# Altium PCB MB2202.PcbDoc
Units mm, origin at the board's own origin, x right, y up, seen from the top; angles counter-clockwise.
Board outline 43 x 31 mm, 4 copper layers (Top Layer, Signal Layer 1, Signal Layer 2, Bottom Layer), stack 0.599 mm thick; 44 components, 36 nets, 160 pads, 698 vias.
Unrouted connection lines stored in the file: 92.
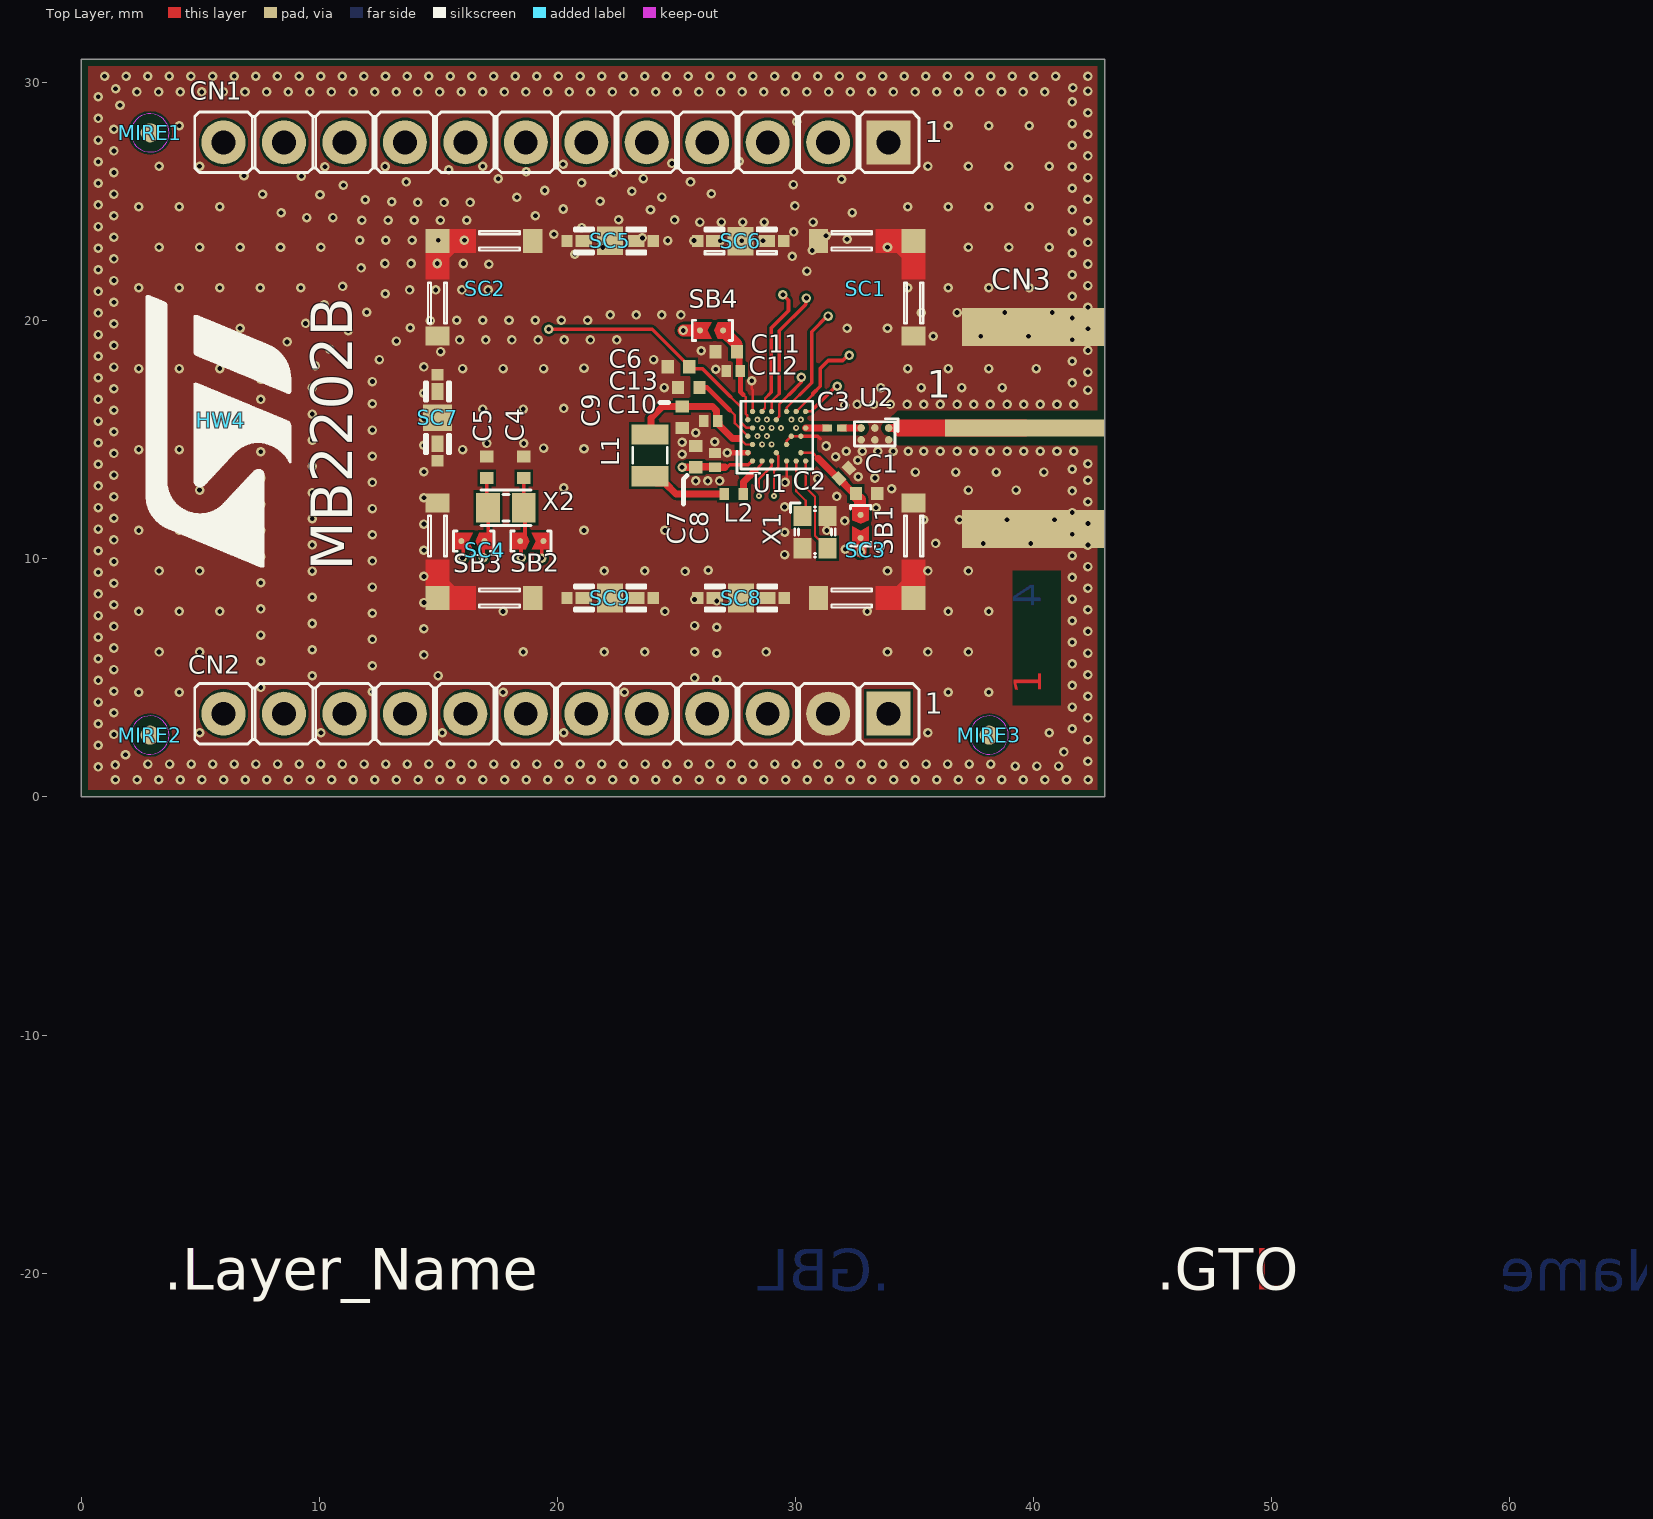
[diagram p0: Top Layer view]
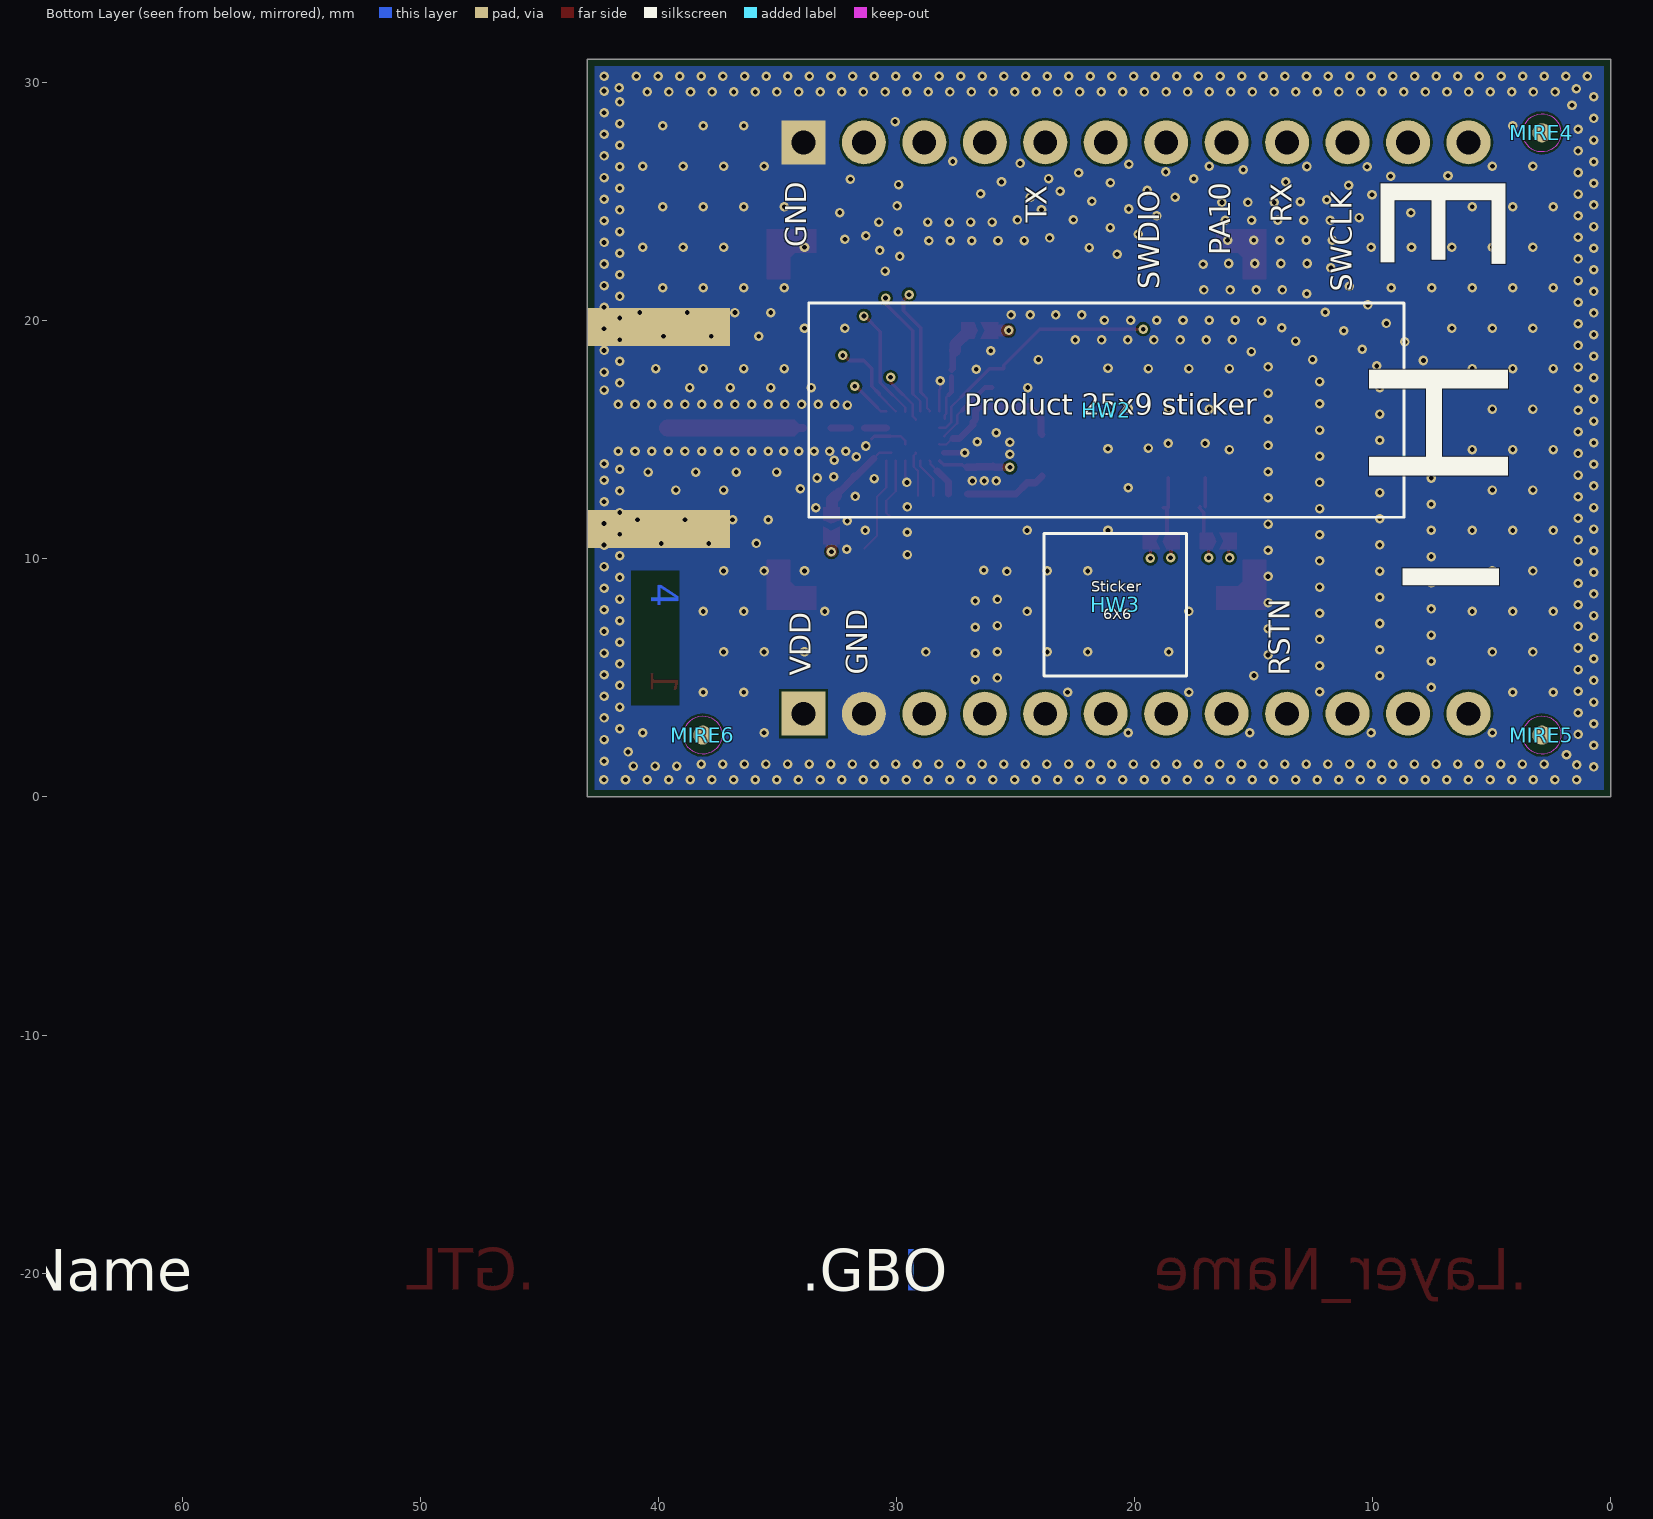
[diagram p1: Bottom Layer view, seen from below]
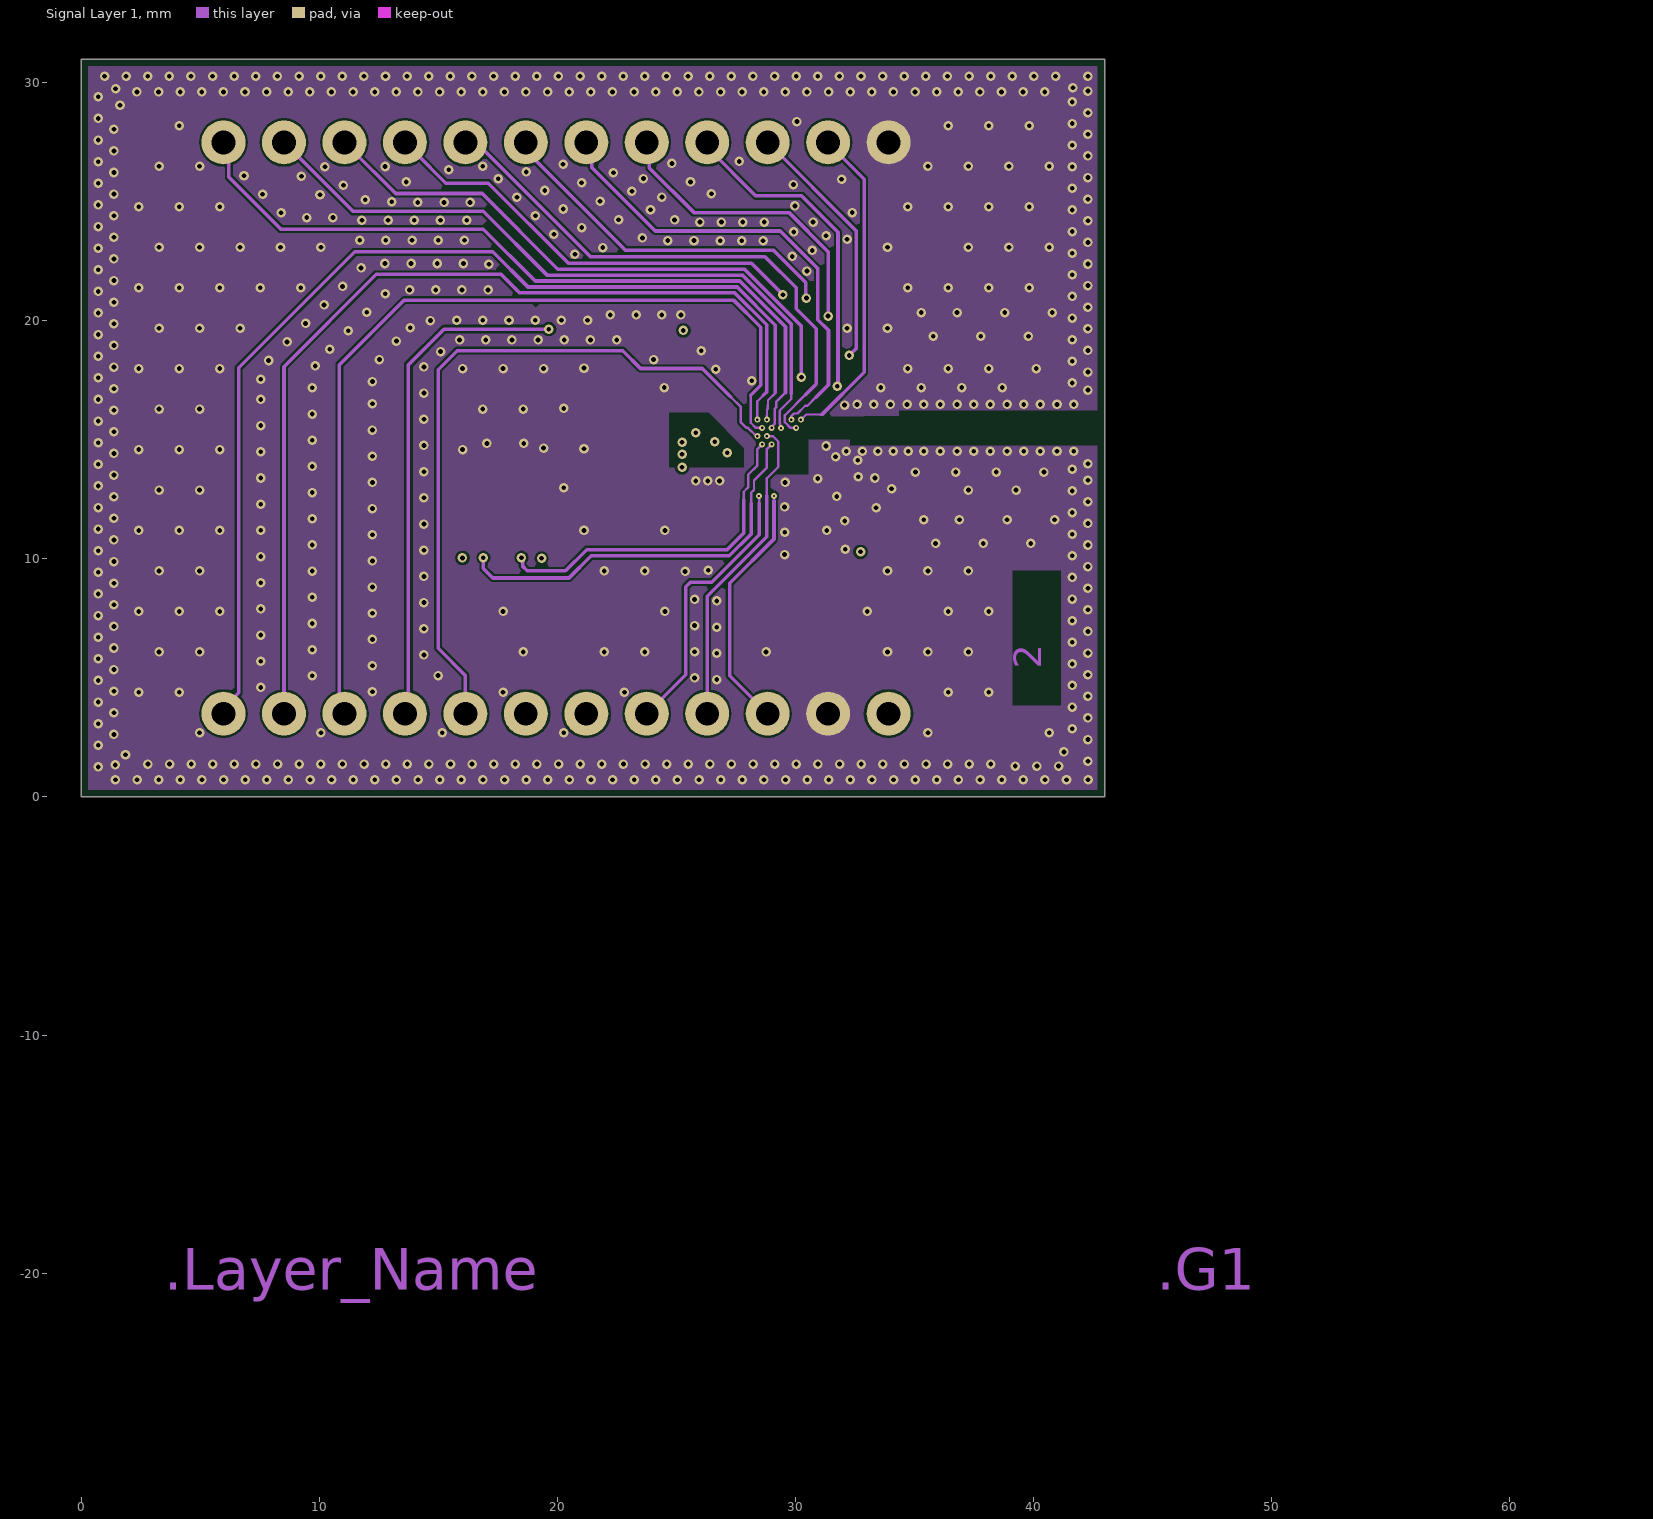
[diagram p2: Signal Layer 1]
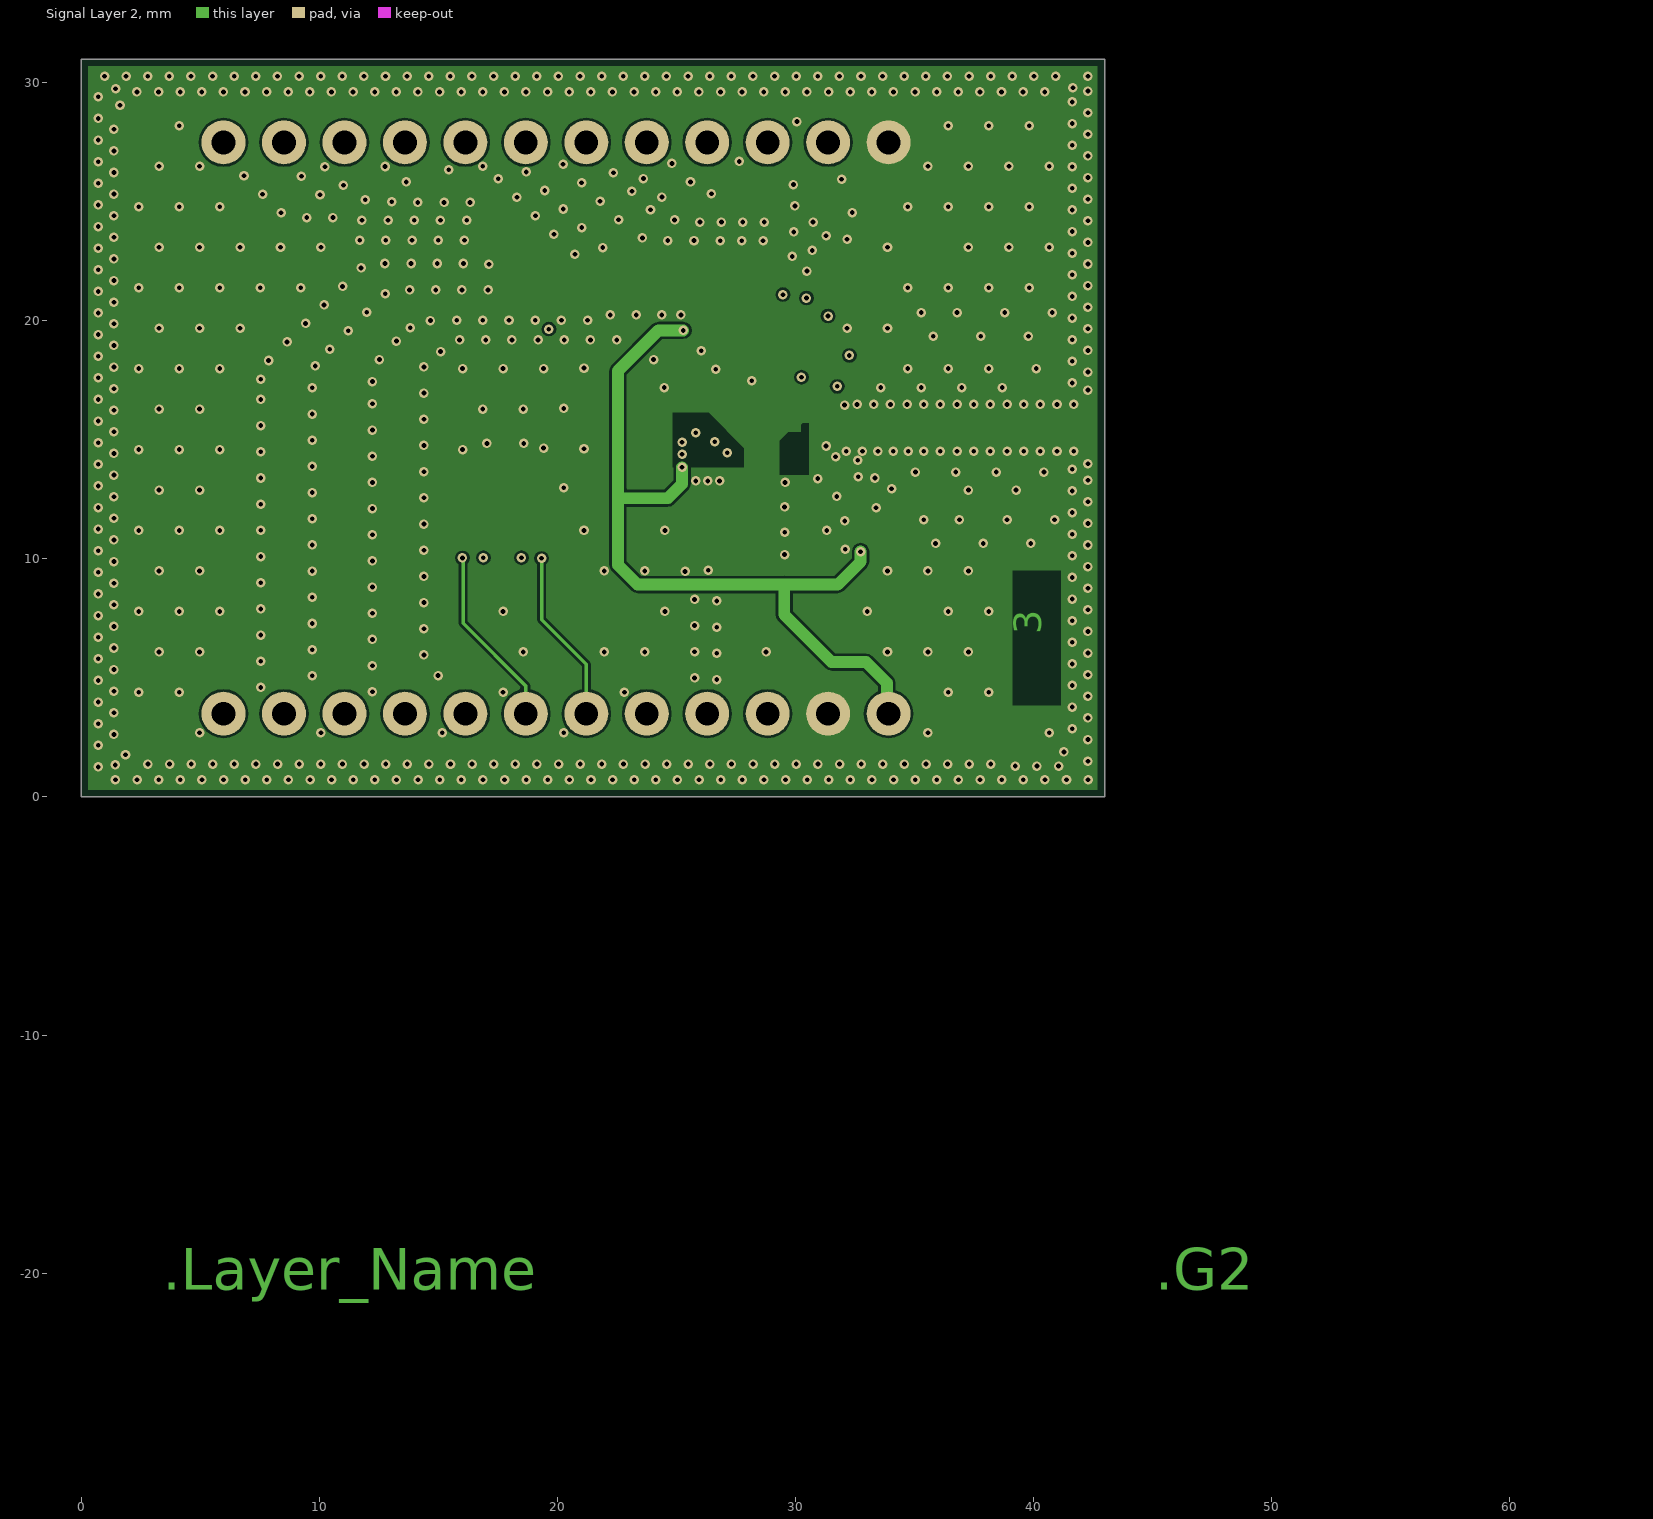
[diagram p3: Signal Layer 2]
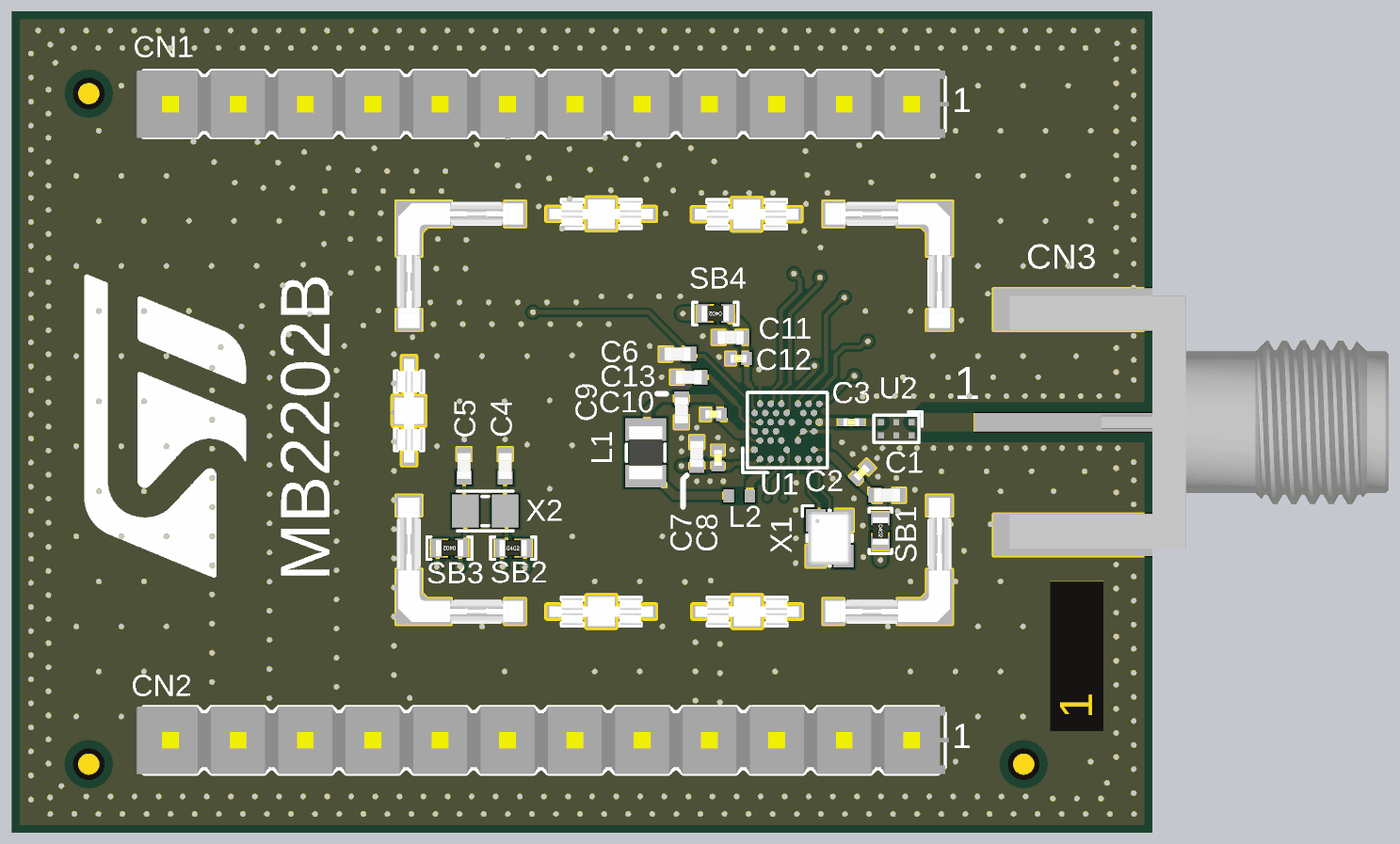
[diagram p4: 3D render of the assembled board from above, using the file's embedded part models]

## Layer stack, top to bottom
Top Solder: solder mask 0.02, Solder Resist, Dk 3.5
Top Layer: signal copper 0.035
Dielectric 1: dielectric 0.102, TU-768 (1x2113), Dk 4.2
Signal Layer 1: signal copper 0.0356
Dielectric2: dielectric 0.254, Tu-768 (2x2113), Dk 4.3
Signal Layer 2: signal copper 0.0356
Dielectric3: dielectric 0.102, TU-768 (1x2113), Dk 4.2
Bottom Layer: signal copper 0.035
Bottom Solder: solder mask 0.02, Solder Resist, Dk 3.5

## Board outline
0,0 0,31 43,31 43,0

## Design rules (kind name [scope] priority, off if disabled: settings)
BoardOutlineClearance [All] p1: gap=0.3 ignorepadtopadclearanceinfootprint=FALSE except(0: Arc-SplitContinuation Track-SplitContinuation SMDPad-SplitContinuation THPad-SplitContinuation Via-SplitContinuation Fill-SplitContinuation Poly-SplitContinuation Region-SplitContinuation Text-SplitContinuation)
Clearance Clearance_RF [InNet('NetC9_2')] p1: gap=0.14 ignorepadtopadclearanceinfootprint=FALSE
Clearance Clearance_RF_1 [InNet('NetC5_1','NetC5_2','NetC9_1')] p2: gap=0.08 ignorepadtopadclearanceinfootprint=FALSE
Clearance [All] p3: gap=0.1 ignorepadtopadclearanceinfootprint=FALSE
HoleToHoleClearance [All] p1: gap=0.15 allowstackedmicrovias=TRUE
MinimumSolderMaskSliver [All] p1: minsoldermaskwidth=0
PlaneClearance [All] p1: clearance=0
PlaneConnect [InNet('GND')] p1: planeconnectstyle=Direct reliefexpansion=0.508 reliefentries=4 reliefconductorwidth=0.254 reliefairgap=0.254
PolygonConnect [InNet('GND')] p1: connectstyle=Direct reliefconductorwidth=0.254 reliefentries=4 polygonreliefangle="90 Angle" airgapwidth=0.254
RoutingVias [All] p1: holewidth=0.2 width=0.4 viastyle="Through Hole" minholewidth=0.2 minwidth=0.4 maxholewidth=0.2 maxwidth=0.4 useviatemplates=TRUE viatemplateguid#1={FA3C43AF-74A2-4DAE-B38C-B4A36A33AEBA} viatemplateguid#2={C3F1866E-02AD-4E07-9877-83EEF2956EBD} viatemplatename#1=v25h10m0 viatemplatename#2=v40h20m0mx0
SMDEntry [All] p1 off: side=TRUE corner=TRUE anyangle=FALSE
SMDNeckDown [All] p1 off: percent=50.000
SMDToCorner [All] p1 off: distance=0
SMDToPlane [All] p1 off: distance=0
SilkToSilkClearance [All] p1: silktosilkclearance=0
SilkToSolderMaskClearance [IsPad] p1: minsilkscreentomaskgap=0 clearancetoexposedcopper=TRUE
SolderMaskExpansion [All] p1: expansion=0.102 istentingtop=FALSE
SupplyNets "Schematic Supply Nets_1" [InNet('VDD')] p1: voltage=0.000
SupplyNets "Schematic Supply Nets" [InNet('GND')] p2: voltage=0.000
ViasUnderSMD [All] p1: allowed=TRUE
Width [All] p1: maxlimit=0.7 minlimit=0.1 preferedwidth=0.1
24 further rules are at their usual default settings.

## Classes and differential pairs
component class Power_Supply: C7 C8 C9 C10 C11 C12 C13 L1 L2 SB4
component class Overview: HW1 HW2 HW3
component class RF_MCU: C1 C2 C3 C4 C5 C6 CN1 CN2 CN3 SB1 SB2 SB3 SC1 SC2 SC3 SC4 SC5 SC6 SC7 SC8 SC9 U1 U2 X1 X2

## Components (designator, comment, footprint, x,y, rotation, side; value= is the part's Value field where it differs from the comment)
C1 "Capacitor" C0402 33,12.75 r180 top value=1uF
C2 "Capacitor" C0201_H0P3#1 32.05,13.6 r225 top value=100nF
C3 "Capacitor" C0201_H0P3#2 31.65,15.494 r0 top value=20pF
C4 "Capacitor" C0402 18.6,13.85 r90 top value=10pF
C5 "Capacitor" C0402 17.05,13.85 r270 top value=10pF
C6 "Capacitor" C0402 25.1,18.075 r180 top value=10nF
C7 "Capacitor" C0402 25.825,14.3 r270 top value=4.7uF
C8 "Capacitor" C0201_H0P3#1 26.625,14.15 r270 top value=100nF
C9 "Capacitor" C0402 25.25,15.95 r90 top value=4.7uF
C10 "Capacitor" C0201_H0P3#1 26.45,15.8 r0 top value=100nF
C11 "Capacitor" C0402 27.1,18.7 r0 top value=1uF
C12 "Capacitor" C0201_H0P3#1 27.4,17.9 r0 top value=100nF
C13 "Capacitor" C0402 25.525,17.2 r0 top value=0.22uF
CN1 "Header 12x1" CON_SAMTEC_TSW-112-07-X-S 19.955,27.5 r180 top locked
CN2 "Header 12x1" CON_SAMTEC_TSW-112-07-X-S 19.955,3.5 r180 top locked
CN3 "SMA-J-P-H-ST-EM1" CON_SMA_AMPHENOL_132415 43,15.5 r90 top value=132415
HW2 "STICKER_PRODUCT" STICKER_PRODUCT_25X9 21.2,16.25 r180 bottom value=N/A
HW3 "STICKER_ES" STICKER_ES_6X6 20.825,8.075 r180 bottom value=N/A
HW4 "Logo" LOGO_ST 5.875,15.825 r90 top
L1 "Inductor" IND_0805_MURATA_LQM21 23.9,14.35 r270 top value=10uH
L2 "Inductor" IND_0402_MURATA_LQG15HSXXXX02_H0P5 27.425,12.725 r0 top value=22nH
MIRE1 "Comment" MIRE_PLACE_SMD_0P8MM 2.9,27.9 r0 top
MIRE2 "Comment" MIRE_PLACE_SMD_0P8MM 2.9,2.6 r0 top
MIRE3 "Comment" MIRE_PLACE_SMD_0P8MM 38.15,2.6 r0 top
MIRE4 "Comment" MIRE_PLACE_SMD_0P8MM 2.9,27.9 r180 bottom
MIRE5 "Comment" MIRE_PLACE_SMD_0P8MM 2.9,2.6 r180 bottom
MIRE6 "Comment" MIRE_PLACE_SMD_0P8MM 38.15,2.6 r180 bottom
SB1 "SB_ON" SOLDER-BRIDGE_R0402-0R 32.75,11.4 r270 top value=0R
SB2 "SB_ON" SOLDER-BRIDGE_R0402-0R 18.9,10.75 r0 top value=0R
SB3 "SB_ON" SOLDER-BRIDGE_R0402-0R 16.5,10.75 r180 top value=0R
SB4 "SB_ON" SOLDER-BRIDGE_R0402-0R 26.525,19.6 r180 top value=0R
SC1 "Shield-clip_S0951-46R" CLIP_HARWIN_S0981-46R 34.975,23.358 r90 top locked value=S0981-46R
SC2 "Shield-clip_S0951-46R" CLIP_HARWIN_S0981-46R 14.975,23.358 r180 top locked value=S0981-46R
SC3 "Shield-clip_S0951-46R" CLIP_HARWIN_S0981-46R 34.975,8.358 r0 top locked value=S0981-46R
SC4 "Shield-clip_S0951-46R" CLIP_HARWIN_S0981-46R 14.975,8.358 r270 top locked value=S0981-46R
SC5 "Shield-clip_S0951-46R" CLIP_HARWIN_S0951-46R 22.225,23.358 r180 top locked value=S0951-46R
SC6 "Shield-clip_S0951-46R" CLIP_HARWIN_S0951-46R 27.71,23.35 r180 top locked value=S0951-46R
SC7 "Shield-clip_S0951-46R" CLIP_HARWIN_S0951-46R 14.975,15.932 r270 top locked value=S0951-46R
SC8 "Shield-clip_S0951-46R" CLIP_HARWIN_S0951-46R 27.725,8.358 r180 top locked value=S0951-46R
SC9 "Shield-clip_S0951-46R" CLIP_HARWIN_S0951-46R 22.225,8.358 r180 top locked value=S0951-46R
U1 "IC_STM32WB09TEF6TR" ICC_WLCSP36_2P83X2P99_P040 29.237,15.197 r90 top value=STM32WB09TEF6TR
U2 "MLPF-WB55-01E3" ICC_CSPG_6BUMPS_1X1P60_P050-P0577 33.35,15.25 r270 top value=MLPF-NRG-01D3
X1 "XTAL_4_PINS" CRY_NX2016SA_4P 30.833,11.125 r270 top value=32MHz
X2 "XTAL_2_PINS" CRY_NX2012SA_2P 17.85,12.15 r180 top value=32.768kHz

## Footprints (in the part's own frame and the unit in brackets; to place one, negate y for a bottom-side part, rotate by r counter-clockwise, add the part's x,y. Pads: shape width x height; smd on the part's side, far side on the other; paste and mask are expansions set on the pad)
C0201_H0P3#1 [mm] "MCD-00699"
  rect 0.4x0.5 smd mask+0.05: 1(-0.3,0) 2(0.3,0)
  body extent -0.32,-0.17 0.32,0.17, height 0.33
C0201_H0P3#2 [mm] "MCD-00699"
  rect 0.4x0.3 smd mask+0.05: 1(-0.3,0) 2(0.3,0)
  body extent -0.32,-0.17 0.32,0.17, height 0.33
C0402 [mm]
  rect 0.51x0.56 smd mask+0.05: 1(-0.45,0) 2(0.45,0)
  body extent -0.5,-0.3 0.5,0.3, height 0.4
CLIP_HARWIN_S0951-46R [mm] "MCD-01587_CLIP-X1"
  rect 0.48x0.5 smd mask+0.1: 1(-1.81,0) 1(1.81,0)
  rect 0.7x0.5 smd mask+0.1: 1(-1.1,0) 1(1.1,0)
  rect 1.1x1.2 smd mask+0.1: 1(0,0)
  silkscreen extent -1.5,-0.55 1.5,0.55, body extent -2.05,-0.65 2.05,0.65, height 1.28
CLIP_HARWIN_S0981-46R [mm] "MCD-02164"
  rect 0.8x1 smd mask+0.05: 1(-4,0)
  rect 1x0.8 smd mask+0.05: 1(0,4)
  rect 1x1 smd mask+0.05: 1(0,0)
  Top Layer region: -1.6,-0.5 0.5,-0.5 0.5,1.6 -0.5,1.6 -0.5,0.7 -0.7,0.5 -1.6,0.5
  silkscreen extent -3.45,-0.4 0.4,3.45, body extent -4.3,-0.46 0.46,4.3, height 1.4
CON_SAMTEC_TSW-112-07-X-S [mm] "MCD-01795"
  rect 1.85x1.85 / inner round 1.85 / far side rect 1.85x1.85 hole 1 mask+0.05: 1(-13.97,0)
  round 1.85 hole 1 mask+0.05: 2(-11.43,0) 3(-8.89,0) 4(-6.35,0) 5(-3.81,0) 6(-1.27,0) 7(1.27,0) 8(3.81,0) 9(6.35,0) 10(8.89,0) 11(11.43,0) 12(13.97,0)
  silkscreen extent -15.24,-1.27 15.18,1.27, body extent -15.37,-1.27 15.24,1.27, height 8.38
CON_SMA_AMPHENOL_132415 [mm] "MCD-04961"
  rect 0.7x6.7 smd mask+0.05: 1(0,3.35)
  rect 1.6x6 smd mask+0.05: 2(-4.25,3) 3(4.25,3)
  rect 1.6x6 smd far side mask+0.05: 4(4.25,3) 5(-4.25,3)
  body extent -4.76,-8.89 4.76,5.38, height 4.08
CRY_NX2012SA_2P [mm]
  rect 1x1.25 smd mask+0.05: 1(-0.75,0) 2(0.75,0)
  silkscreen extent -1.05,-0.75 1.05,0.75, body extent -1.05,-0.63 1.05,0.63, height 0.6
CRY_NX2016SA_4P [mm]
  rect 0.85x0.75 smd mask+0.05: 1(-0.675,-0.525) 2(0.675,-0.525) 3(0.675,0.525) 4(-0.675,0.525)
  silkscreen extent -1.22,-1.02 1.05,0.85, body extent -1.05,-0.85 1.05,0.85, height 0.7
ICC_CSPG_6BUMPS_1X1P60_P050-P0577 [mm] "MCD-03490"
  round 0.32 smd paste-2539.97 mask-0.05: A1(-0.25,0.577) A2(-0.25,0) A3(-0.25,-0.577) B1(0.25,0.577) B2(0.25,0) B3(0.25,-0.577)
  silkscreen extent -0.64,-0.85 0.51,0.97, body extent -0.51,-0.81 0.51,0.81, height 0.7
ICC_WLCSP36_2P83X2P99_P040 [mm] "MCD-04889"
  round 0.225 smd paste+0.012 mask+0.032: A2(-0.736,1.226) A4(-0.043,1.226) A6(0.65,1.226) B1(-1.082,1.026) B3(-0.389,1.026) B5(0.304,1.026) B7(0.996,1.026) C4(-0.043,0.826) C6(0.65,0.826) D1(-1.082,0.626) D3(-0.389,0.626) D5(0.303,0.626) D7(0.996,0.626) E4(-0.043,0.426) E6(0.65,0.426) F1(-1.082,0.226) F3(-0.389,0.226) F5(0.303,0.226) F7(0.996,0.226) G2(-0.736,0.025) G6(0.65,0.025) H5(0.303,-0.175) J1(-1.082,-0.404) J3(-0.389,-0.404) J7(0.996,-0.404) K4(-0.043,-0.605) K6(0.65,-0.605) L1(-1.082,-0.805) L5(0.303,-0.805) L7(0.996,-0.805) M2(-0.736,-1.005) M4(-0.043,-1.005) M6(0.65,-1.005) N1(-1.083,-1.205) N5(0.303,-1.205) N7(0.996,-1.205)
  silkscreen extent -1.6,-1.51 1.43,1.68, body extent -1.43,-1.51 1.43,1.51, height 0.44
IND_0402_MURATA_LQG15HSXXXX02_H0P5 [mm] "MCD-03474"
  rect 0.4x0.5 smd mask+0.05: 1(-0.4,0) 2(0.4,0)
  body extent -0.55,-0.28 0.55,0.28, height 0.55
IND_0805_MURATA_LQM21 [mm] "MCD-02317"
  rect 0.85x1.55 smd mask+0.05: 1(-0.875,0) 2(0.875,0)
  silkscreen extent -0.33,-0.72 0.33,0.72, body extent -1.1,-0.72 1.1,0.72, height 1.45
LOGO_ST [mm]
  silkscreen extent -6.18,-2.95 5.25,3.14
MIRE_PLACE_SMD_0P8MM [mm]
  round 0.8 smd paste-10 mask+0.2: 1(0,0)
  Top Layer keep-out circle w0.01: c0,0 r0.804
SOLDER-BRIDGE_R0402-0R [mil] "MCD-01619"
  round 10 smd paste-393.7: 1(-17.72,0) 2(20.67,0)
  Top Layer region: 1.48,13.78 8.37,0 1.48,-13.78 30.51,-13.78 30.51,13.78
  Top Layer region: -30.51,-13.78 -30.51,13.78 -8.86,13.78 -2.95,0 -8.86,-13.78
  silkscreen extent -33,-17 33,17, body extent -20,-12 20,12, height 14
STICKER_ES_6X6 [mm] "Sticker to mention board QR code 8X8"
  silkscreen extent -3,-3 3,3
STICKER_PRODUCT_25X9 [mm] "Sticker to mention board CPN code"
  silkscreen extent -12.5,-4.5 12.5,4.5

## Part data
C1 C11: library part MCD-03432, "Capacitor, MLCC, 1uF, X7R, 6.3V,+/- 10%, 0402, T=0.5mm", Manufacturer=MURATA, Manufacturer_Part_Number=GRM155R70J105KA12, Package=0402
C2 C8 C10 C12: library part MCD-01535, "Capacitor, MLCC,100nF, 10V, X5R, +/-10%, 0201, T=0.3mm", Manufacturer=MURATA, Manufacturer_Part_Number=GRM033R61A104KE15, Package=0201
C3: library part MCD-03543, "Capacitor, MLCC, 20pF, 25V, COG, +/-2%, 0201, T=0.3mm", Manufacturer=MURATA, Manufacturer_Part_Number=GJM0335C1E200GB01, Package=0201
C4 C5: library part MCD-00015, "Capacitor, MLCC, 10pF, 50V, NPO, +/-5%, 0402, T=0.5mm", Manufacturer=YAGEO, Manufacturer_Part_Number=CC0402JRNPO9BN100, Package=0402
C6: library part MCD-00011, "Capacitor, MLCC, 10nF, 16V, X7R, +/-10%, 0402, T=0.5mm", Manufacturer=YAGEO, Manufacturer_Part_Number=CC0402KRX7R7BB103, Package=0402
C7 C9: library part MCD-03431, "Capacitor, MLCC, 4.7uF, X5R, 10V, +/-20%, 0402, T=0.5mm", Manufacturer=MURATA, Manufacturer_Part_Number=GRM155R61A475MEAAD, Package=0402
C13: library part MCD-03483, "Capacitor, MLCC, 0.22uF, X5R, 6.3V, +/-10%, 0402, T=0.5mm", Manufacturer=YAGEO, Manufacturer_Part_Number=CC0402KRX5R5BB224, Package=0402
CN1 CN2: library part MCD-01795, "Header, 12x1, 2.54mm, VR, TH, T=5.84mm/2.54mm", Manufacturer=SAMTEC, Manufacturer_Part_Number=TSW-112-07-T-S
CN3: library part MCD-04961, "Jack_SMA, VR, PCB edge, 50R, T=7.92mm", Manufacturer=AMPHENOL, Manufacturer_Part_Number=132415
HW2: library part MCD-00547, "Sticker product, 25x9mm", Manufacturer=N/A, Manufacturer_HQ_COO=Unknown
HW3: library part MCD-00234, "Sticker ES, 6x6mm", Manufacturer=N/A
HW4: library part MCD-00625, "\"STMicroelectronics\" logo footprint for PCB"
L1: library part MCD-03438, "Inductor, MLCC, 10uH, +/-20%, 300mA, 845mR, 0805, T=1.45mm", Manufacturer=MURATA, Manufacturer_Part_Number=LQM21DN100M70L, Package=0805
L2: library part MCD-03439, "Inductor, MLCC, 22nH, +/-2%, 350mA, 0.58R, 0402, T=1.45mm", Manufacturer=MURATA, Manufacturer_Part_Number=LQW15AN22NG00, Package=0402
SB1 SB2 SB3 SB4: library part MCD-01618, "Resistor, 0R, SB0402, 5%, 0.063W", Manufacturer=YAGEO, Manufacturer_Part_Number=RC0402JR-070RL, Package=0402
SC1 SC2 SC3 SC4: library part MCD-02164, "Shield clip Harwin S0981-46R to fix RF shielded cavity", Manufacturer=HARWIN, Manufacturer_Part_Number=S0981-46R, Package=0.8x4.7x1.4mm
SC5 SC6 SC7 SC8 SC9: library part MCD-01587, "RFI shield clip mini TIN SMD", Manufacturer=HARWIN, Manufacturer_Part_Number=S0951-46R, Package=1.1x3.9mm
U1: library part MCD-04889, "MCU, ARM Cortex-M0+ 32-bit, 512KB Flash, 64KB RAM, With Crypto", Manufacturer=STMICROELECTRONICS, Manufacturer_Part_Number=STM32WB09TEF6TR, Package=WLCSP36
U2: library part MCD-03490, "2.4 GHz low pass filter matched to BLUENRG-LP-LPS", Manufacturer=STMICROELECTRONICS, Manufacturer_Part_Number=MLPF-NRG-01D3, Package=CSP
X1: library part MCD-01446, "Crystal, 32MHz, 8pF, +/-10ppm, 60R, 2x1.6mm", Manufacturer=NDK, Manufacturer_Part_Number=NX2016SA-32MHZ-EXS00A-CS06654, Package=2x1.6mm
X2: library part MCD-01445, "Crystal, 32.768kHz, 7pF, +/-20ppm, 80K, 2.05x1.2mm", Manufacturer=NDK, Manufacturer_Part_Number=NX2012SA-32.768KHZ-EXS00A-MU00389, Package=2.05x1.2mm

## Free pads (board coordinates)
  round 0.508 on Mech16: 1(15.17,-27.648) 1(64.017,-27.648)

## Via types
v1: diameter 0.4, hole 0.2, Top Layer to Bottom Layer, tented both sides, 684 vias
v2: diameter 0.25, hole 0.1, Top Layer to Signal Layer 1, tented both sides, 14 vias

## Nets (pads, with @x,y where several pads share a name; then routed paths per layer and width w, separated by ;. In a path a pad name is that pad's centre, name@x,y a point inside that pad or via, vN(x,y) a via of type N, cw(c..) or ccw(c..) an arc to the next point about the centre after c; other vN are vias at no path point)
GND: C1.1 C2.1 C4.2 C5.1 C6.2 C7.1 C8.1 C9.1 C10.1 C11.1 C12.1 C13.1 CN1.1 CN2.2 CN3.2 CN3.3 CN3.4 CN3.5 SC1.1 SC2.1 SC3.1 SC4.1 SC5.1 SC6.1 SC7.1 SC8.1 SC9.1 U1.A2 U1.B7 U1.J1 U1.J3 U1.K4 U1.M4 U2.A2 U2.B1 U2.B2 U2.B3 X1.2 X1.4 | length 4.8
  Top Layer w0.1: v1(28.175,17.485) 28.175,17.153 28.212,17.116 U1.B7 ; v1(29.574,13.214) 29.574,13.295 29.642,13.364 U1.J1@29.642,14.12 ; U1.J3@29.642,14.813 29.642,14.96 29.842,15.16 U1.M4@30.242,15.16
  Top Layer w0.148: U1.M4@30.247,15.158 30.942,15.158 31.05,15.05
  Top Layer w0.25: v1(27.15,14.461) 27.55,14.461 ; 27.573,14.461 U1.A2@28.012,14.461
  other v1: 1.447,0.72 2.355,0.72 3.263,0.72 4.171,0.72 5.079,0.72 5.987,0.72 6.895,0.72 7.803,0.72 8.711,0.72 9.619,0.72 10.527,0.72 11.435,0.72 12.343,0.72 13.251,0.72 14.159,0.72 15.067,0.72 15.975,0.72 16.883,0.72 17.791,0.72 18.699,0.72 19.607,0.72 20.515,0.72 21.423,0.72 22.331,0.72 23.239,0.72 24.147,0.72 25.055,0.72 25.963,0.72 26.871,0.72 27.779,0.72 28.687,0.72 29.595,0.72 30.503,0.72 31.411,0.72 32.319,0.72 33.227,0.72 34.135,0.72 35.043,0.72 35.951,0.72 36.859,0.72 37.767,0.72 38.675,0.72 39.583,0.72 40.491,0.72 41.399,0.72 42.307,0.72 0.72,1.264 39.25,1.3 40.158,1.3 41.066,1.3 1.441,1.347 2.809,1.38 3.717,1.38 4.625,1.38 5.533,1.38 6.441,1.38 7.349,1.38 8.257,1.38 9.165,1.38 10.073,1.38 10.981,1.38 11.889,1.38 12.797,1.38 13.705,1.38 14.613,1.38 15.521,1.38 16.429,1.38 17.337,1.38 18.245,1.38 19.153,1.38 20.061,1.38 20.969,1.38 21.877,1.38 22.785,1.38 23.693,1.38 24.601,1.38 25.509,1.38 26.417,1.38 27.325,1.38 28.233,1.38 29.141,1.38 30.049,1.38 30.957,1.38 31.865,1.38 32.773,1.38 33.681,1.38 34.589,1.38 35.497,1.38 36.405,1.38 37.313,1.38 38.221,1.38 42.3,1.505 1.867,1.776 41.293,1.894 0.72,2.172 42.3,2.413 1.38,2.626 4.979,2.695 10.079,2.695 15.179,2.695 20.279,2.695 35.579,2.695 40.679,2.695 41.64,2.867 0.72,3.08 42.3,3.321 1.38,3.534 41.64,3.775 0.72,3.988 42.3,4.229 2.429,4.395 4.129,4.395 17.729,4.395 22.829,4.395 36.429,4.395 38.129,4.395 12.239,4.416 1.38,4.442 7.55,4.6 41.64,4.683 0.72,4.896 26.702,4.933 25.775,5 9.714,5.087 15,5.1 42.3,5.137 1.38,5.35 12.239,5.516 41.64,5.591 7.55,5.7 0.72,5.804 14.403,5.965 26.702,6.033 42.3,6.045 3.279,6.095 4.979,6.095 18.579,6.095 21.979,6.095 23.679,6.095 25.775,6.1 28.779,6.095 33.879,6.095 35.579,6.095 37.279,6.095 9.714,6.187 1.38,6.258 41.64,6.499 12.239,6.616 0.72,6.712 7.55,6.8 42.3,6.953 14.403,7.065 26.702,7.133 1.38,7.166 25.775,7.2 9.714,7.287 41.64,7.407 0.72,7.62 12.239,7.716 2.429,7.795 4.129,7.795 5.829,7.795 17.729,7.795 24.529,7.795 33.029,7.795 36.429,7.795 38.129,7.795 42.3,7.861 7.55,7.9 1.38,8.074 14.403,8.165 26.702,8.233 25.775,8.3 41.64,8.315 9.714,8.387 0.72,8.528 42.3,8.769 12.239,8.816 1.38,8.982 7.55,9 41.64,9.223 14.403,9.265 0.72,9.436 25.375,9.475 3.279,9.495 4.979,9.495 9.714,9.487 21.979,9.495 23.679,9.495 33.879,9.495 35.579,9.495 37.279,9.495 26.35,9.525 42.3,9.677 1.38,9.89 12.239,9.916 7.55,10.1 41.64,10.131 29.554,10.185 0.72,10.344 14.403,10.365 32.106,10.408 9.714,10.587 42.3,10.585 35.9,10.65 37.9,10.65 39.9,10.65 1.38,10.798 12.239,11.016 41.64,11.039 29.56,11.12 2.429,11.195 4.129,11.195 5.829,11.195 7.55,11.2 21.129,11.195 24.529,11.195 31.329,11.195 0.72,11.252 14.403,11.465 42.3,11.493 32.084,11.599 35.4,11.65 36.9,11.65 38.9,11.65 40.9,11.65 9.714,11.687 1.38,11.706 41.64,11.947 12.239,12.116 0.72,12.16 33.4,12.15 29.555,12.185 7.55,12.3 42.3,12.401 14.403,12.565 1.38,12.614 31.75,12.625 9.714,12.787 41.64,12.855 3.279,12.895 4.979,12.895 37.279,12.895 39.279,12.895 34.05,12.95 20.283,12.985 0.72,13.068 12.239,13.216 25.825,13.275 26.325,13.275 26.825,13.275 42.3,13.309 30.948,13.373 7.55,13.4 33.35,13.4 32.65,13.45 1.38,13.522 14.403,13.665 35.05,13.65 36.75,13.65 38.45,13.65 40.45,13.65 41.64,13.763 9.714,13.887 0.72,13.976 42.3,13.995 32.625,14.15 31.7,14.294 12.239,14.316 25.25,14.4 1.38,14.43 7.55,14.5 32.15,14.525 32.825,14.525 33.475,14.525 34.125,14.525 34.75,14.525 35.402,14.525 36.1,14.525 36.8,14.525 37.5,14.525 38.2,14.525 38.9,14.525 39.6,14.525 40.3,14.525 41,14.525 41.7,14.525 2.429,14.595 4.129,14.595 5.829,14.595 16.029,14.595 21.129,14.63 19.429,14.655 31.3,14.744 14.403,14.765 17.05,14.85 18.6,14.85 0.72,14.884 25.25,14.9 26.625,14.925 9.714,14.987 25.825,15.3 1.38,15.338 12.239,15.416 7.55,15.6 0.72,15.792 14.403,15.865 9.714,16.087 1.38,16.246 3.279,16.295 4.979,16.295 16.879,16.295 18.579,16.295 20.279,16.32 32.077,16.465 32.602,16.49 33.302,16.49 34.002,16.49 34.702,16.49 35.402,16.49 36.1,16.49 36.8,16.49 37.5,16.49 38.2,16.49 38.9,16.49 39.6,16.49 40.3,16.49 41,16.49 41.7,16.49 12.239,16.516 0.72,16.7 7.55,16.7 14.403,16.965 42.3,17.095 1.38,17.154 9.714,17.187 24.5,17.2 33.6,17.2 35.3,17.2 37,17.2 38.7,17.2 41.64,17.395 12.239,17.45 7.55,17.55 0.72,17.608 42.3,17.849 26.665,17.965 2.429,17.995 4.129,17.995 5.829,17.995 16.029,17.995 17.729,17.995 19.429,17.995 34.729,17.995 36.429,17.995 38.129,17.995 40.129,17.995 21.129,18.02 1.38,18.062 14.403,18.065 9.834,18.11 41.64,18.303 7.877,18.336 12.534,18.375 24.05,18.375 0.72,18.516 15.103,18.71 26.05,18.75 42.3,18.757 10.448,18.806 1.38,18.97 8.655,19.114 13.25,19.15 15.9,19.2 17,19.2 18.1,19.2 19.2,19.2 20.3,19.2 21.4,19.2 22.5,19.2 41.64,19.211 35.8,19.35 37.8,19.35 39.8,19.35 0.72,19.424 11.225,19.584 42.3,19.665 3.279,19.695 4.979,19.695 6.679,19.695 13.829,19.711 32.179,19.695 33.879,19.695 1.38,19.878 9.433,19.891 14.679,20.011 15.779,20.025 16.879,20.025 17.979,20.025 19.079,20.025 20.179,20.025 21.279,20.025 41.64,20.119 22.229,20.25 23.325,20.25 24.4,20.25 25.2,20.25 0.72,20.332 35.3,20.35 36.8,20.35 38.8,20.35 40.8,20.35 12.003,20.362 42.3,20.573 10.211,20.669 1.38,20.786 41.64,21.027 12.781,21.139 0.72,21.24 13.8,21.3 14.9,21.3 16,21.3 17.1,21.3 2.429,21.395 4.129,21.395 5.829,21.395 7.529,21.395 9.229,21.395 34.729,21.395 36.429,21.395 38.129,21.395 39.829,21.395 10.989,21.447 42.3,21.481 1.38,21.694 41.64,21.935 30.495,22.092 0.72,22.148 11.766,22.225 17.137,22.382 42.3,22.389 12.766,22.411 13.866,22.411 14.966,22.411 16.066,22.411 1.38,22.602 29.877,22.709 20.75,22.8 41.64,22.843 30.721,22.959 0.72,23.056 3.279,23.095 4.979,23.095 6.679,23.095 8.379,23.095 10.079,23.095 21.92,23.08 33.879,23.095 37.279,23.095 38.979,23.095 40.679,23.095 42.3,23.297 24.65,23.375 25.75,23.375 26.853,23.371 27.753,23.371 28.653,23.371 11.705,23.389 12.805,23.389 13.905,23.389 15.005,23.389 16.105,23.389 32.179,23.425 23.582,23.487 1.38,23.51 31.3,23.575 19.865,23.642 29.943,23.737 41.64,23.751 21.035,23.922 0.72,23.964 26,24.15 26.9,24.15 27.8,24.15 28.7,24.15 30.75,24.15 42.3,24.205 11.8,24.225 12.9,24.225 14,24.225 15.1,24.225 16.2,24.225 24.935,24.239 22.581,24.25 9.483,24.339 10.583,24.339 1.38,24.418 19.087,24.42 8.402,24.54 32.4,24.55 23.923,24.669 41.64,24.659 20.257,24.7 2.429,24.795 4.129,24.795 5.829,24.795 34.729,24.795 36.429,24.795 38.129,24.795 39.829,24.795 29.989,24.831 0.72,24.872 14.15,24.975 15.25,24.975 16.345,24.975 13.05,25 21.803,25.028 11.942,25.089 42.3,25.113 18.309,25.198 24.405,25.203 10.039,25.295 1.38,25.326 7.624,25.318 26.483,25.339 23.145,25.447 19.479,25.478 41.64,25.567 11.023,25.693 29.925,25.725 0.72,25.78 21.025,25.806 13.661,25.839 25.603,25.839 31.95,25.95 17.531,25.976 23.628,25.981 42.3,26.021 9.261,26.073 6.846,26.095 1.38,26.234 22.367,26.225 18.701,26.256 15.45,26.346 10.245,26.471 3.279,26.495 4.979,26.495 12.771,26.485 16.879,26.495 35.579,26.495 37.279,26.495 38.979,26.495 40.679,26.495 41.64,26.475 20.248,26.584 24.825,26.616 0.72,26.688 27.65,26.7 42.3,26.929 1.38,27.142 41.64,27.383 0.72,27.596 42.3,27.837 1.38,28.05 4.129,28.195 36.429,28.195 38.129,28.195 39.829,28.195 41.64,28.291 30.075,28.375 0.72,28.504 42.3,28.745 1.637,29.062 41.64,29.199 0.72,29.412 2.348,29.62 3.256,29.62 4.164,29.62 5.072,29.62 5.98,29.62 6.888,29.62 7.796,29.62 8.704,29.62 9.612,29.62 10.52,29.62 11.428,29.62 12.336,29.62 13.244,29.62 14.152,29.62 15.06,29.62 15.968,29.62 16.876,29.62 17.784,29.62 18.692,29.62 19.6,29.62 20.508,29.62 21.416,29.62 22.324,29.62 23.232,29.62 24.14,29.62 25.048,29.62 25.956,29.62 26.864,29.62 27.772,29.62 28.68,29.62 29.588,29.62 30.496,29.62 31.404,29.62 32.312,29.62 33.22,29.62 34.128,29.62 35.036,29.62 35.944,29.62 36.852,29.62 37.76,29.62 38.668,29.62 39.576,29.62 40.484,29.62 42.3,29.653 1.45,29.75 41.67,29.795 0.986,30.28 1.894,30.28 2.802,30.28 3.71,30.28 4.618,30.28 5.526,30.28 6.434,30.28 7.342,30.28 8.25,30.28 9.158,30.28 10.066,30.28 10.974,30.28 11.882,30.28 12.79,30.28 13.698,30.28 14.606,30.28 15.514,30.28 16.422,30.28 17.33,30.28 18.238,30.28 19.146,30.28 20.054,30.28 20.962,30.28 21.87,30.28 22.778,30.28 23.686,30.28 24.594,30.28 25.502,30.28 26.41,30.28 27.318,30.28 28.226,30.28 29.134,30.28 30.042,30.28 30.95,30.28 31.858,30.28 32.766,30.28 33.674,30.28 34.582,30.28 35.49,30.28 36.398,30.28 37.306,30.28 38.214,30.28 39.122,30.28 40.03,30.28 40.938,30.28 42.3,30.275
IPF_IN: C3.2 U2.A3 | length 0.8
  Top Layer w0.3: C3.2 U2.A3@32.773,15.494
NetL1_2: L1.2 L2.1 | length 3.4
  Top Layer w0.3: L1.2 24.175,13.2 24.525,13.2 25,12.725 L2.1
PA0: CN1.3 U1.L7 | length 14.3
  Top Layer w0.1: U1.L7@30.042,16.199 30.746,16.903
  Top Layer w0.15: 30.746,16.903 30.746,16.95 31.05,17.254 31.05,18 31.386,18.336 31.994,18.336 32.209,18.55 v1(32.275,18.55)
  Signal Layer 1 w0.15: CN1.3 32.575,23.77 32.575,18.851 v1@32.275,18.551
PA1: CN1.5 U1.J7 | length 17.7
  Top Layer w0.1: U1.J7@29.646,16.189 29.646,16.357 30.192,16.903
  Top Layer w0.15: 30.192,16.903 30.696,17.407 30.696,19.546 31.352,20.202 v1(31.384,20.202)
  Signal Layer 1 w0.15: CN1.5@23.65,27.6 23.875,27.375 23.875,26.425 25.75,24.55 29.74,24.55 31.394,22.897 v1@31.394,20.204
PA2: CN1.7 U1.F7 | length 20.4
  Top Layer w0.1: U1.F7@29.013,16.199 29.013,16.624 29.337,16.948
  Top Layer w0.15: 29.337,16.948 29.337,19.587 30.44,20.69 30.44,20.929 v1(30.471,20.96)
  Signal Layer 1 w0.15: CN1.7 18.685,27.155 22.865,22.975 29.081,22.975 30.446,21.61 v1@30.446,20.991
PA3: CN1.10 U1.G6 | length 26.9
  Top Layer w0.1: U1.G6@29.213,15.852 29.213,15.872 29.327,15.986 29.327,16.49 29.739,16.903
  Top Layer w0.15: 29.739,16.903 30.262,17.426 v1(30.262,17.632) v1@30.215,17.585
  Signal Layer 1 w0.15: CN1.10@10.9,27.25 11.315,27.25 13.215,25.35 16.858,25.35 20.033,22.175 27.875,22.175 30.262,19.788 v1(30.262,17.632)
PA8: CN1.4 U1.N7 | length 15.4
  Top Layer w0.1: U1.N7@30.442,16.199 30.661,16.199 30.824,16.362
  Top Layer w0.15: 30.824,16.362 31.715,17.253 v1(31.769,17.253)
  Signal Layer 1 w0.15: CN1.4 26.305,27.295 28.35,25.25 30.275,25.25 31.8,23.725 31.8,17.284 v1(31.769,17.253)
PA9: CN1.6 U1.K6 | length 19.3
  Signal Layer 1 w0.1: v2(29.842,15.852) 29.842,16 29.952,16.109 30.097,16.109 30.424,16.436 30.516,16.436 30.878,16.798
  Signal Layer 1 w0.15: CN1.6@21.2,27.05 21.462,26.788 21.462,26.438 24.125,23.775 29.375,23.775 30.95,22.2 30.95,20.05 31.4,19.6 31.4,17.32 30.878,16.798
PA10: CN1.8 U1.L5 | length 23.5
  Signal Layer 1 w0.1: v2(30.043,15.506) 29.8,15.506 29.567,15.738 29.567,15.756 29.565,15.758 29.565,16.031 30.438,16.903
  Signal Layer 1 w0.15: CN1.8 16.456,27.189 16.911,27.189 21.4,22.7 28.731,22.7 30.042,21.389 30.042,20.508 30.886,19.664 30.886,17.352 30.438,16.903
PA11: CN1.2 U1.M6 | length 13.8
  Signal Layer 1 w0.1: v2(30.242,15.852) 30.463,16.066 30.504,16.066 31.082,16.057 ccw(c31.083,16.157) 31.083,16.057 31.117,16.057 31.131,16.07
  Signal Layer 1 w0.15: 31.131,16.07 32.9,17.839 32.9,25.95 31.385,27.465 CN1.2
PB0: CN1.9 U1.D7 | length 23.7
  Top Layer w0.1: U1.D7@28.613,16.199 28.613,16.226 28.733,16.347 28.733,16.741 28.895,16.903
  Top Layer w0.15: 28.895,16.903 29.002,17.009 29.002,19.702 29.721,20.421 29.721,20.868 v1(29.487,21.102)
  Signal Layer 1 w0.15: CN1.9@13.7,27.05 14.055,27.05 15.316,25.789 17.112,25.789 20.476,22.425 28.164,22.425 v1(29.487,21.102)
PB1: CN2.12 U1.E6 | length 44.6
  Signal Layer 1 w0.1: v2(28.813,15.852) 28.816,16.276 28.856,16.315 28.858,16.668 29.168,16.973
  Signal Layer 1 w0.15: CN2.12@6.1,3.6 6.1,3.855 6.625,4.38 6.625,18.025 11.5,22.9 17.3,22.9 18.775,21.425 27.564,21.425 29.168,19.821 29.168,16.973
PB2: CN2.10 U1.D5 | length 38.8
  Signal Layer 1 w0.1: 28.137,16.877 28.137,15.717 28.349,15.506 v2(28.613,15.506)
  Signal Layer 1 w0.15: CN2.10 10.85,3.715 10.85,18.15 13.575,20.875 27.407,20.875 28.55,19.732 28.55,17.289 28.137,16.877
PB3: CN2.11 U1.C6 | length 41.3
  Signal Layer 1 w0.1: v2(28.412,15.853) 28.413,16.625 28.666,16.878
  Signal Layer 1 w0.15: CN2.11@8.4,3.75 8.525,3.875 8.525,18.075 12.406,21.956 17.1,21.956 ; 17.113,21.956 17.644,21.956 18.425,21.175 27.461,21.175 28.8,19.836 28.8,17.012 28.666,16.878
PB4: CN1.12 U1.F5 | length 31.9
  Signal Layer 1 w0.1: v2(29.013,15.506) 29.013,15.547 29.149,15.683 29.149,16.318 29.213,16.381 29.213,16.607 29.593,16.988
  Signal Layer 1 w0.15: CN1.12@5.85,27.35 6.212,26.988 6.212,26.038 8.4,23.85 16.9,23.85 19.075,21.675 27.668,21.675 29.593,19.75 29.593,16.988
PB5: CN1.11 U1.H5 | length 29
  Signal Layer 1 w0.1: v2(29.407,15.496) 29.379,15.525 29.379,15.645 29.349,15.674 29.349,16.235 29.843,16.729 29.843,16.939
  Signal Layer 1 w0.15: CN1.11@8.575,27.45 11.425,24.6 16.9,24.6 19.575,21.925 27.771,21.925 29.843,19.853 29.843,16.939
PB6: CN2.8 U1.C4 | length 30.5
  Signal Layer 1 w0.1: 27.286,16.814 27.719,16.381 27.719,15.736 27.949,15.506 28.016,15.506 28.363,15.16 v2(28.413,15.16)
  Signal Layer 1 w0.15: CN2.8 16.145,5.105 15,6.25 15,17.95 15.8,18.75 22.751,18.75 23.501,18 26.1,18 27.286,16.814
PB7: CN2.4 U1.E4 | length 13.2
  Signal Layer 1 w0.1: 28.803,12.661 28.803,13.384 29.287,13.868 29.287,14.933 29.061,15.16 v2(28.813,15.16)
  Signal Layer 1 w0.15: CN2.4 26.305,8.43 28.8,10.925 28.8,12.661
PB12: CN2.6 SB2.2 | length 8
  Top Layer w0.15: v1@19.35,10.011 SB2.2@19.35,10.733
  Signal Layer 2 w0.15: v1@19.35,10.022 19.35,7.45 21.225,5.575 CN2.6
  other v1: 19.349,10.026
PB13: CN2.7 SB3.2 | length 8.8
  Top Layer w0.15: v1@16.05,10.031 SB3.2@16.05,10.713
  Signal Layer 2 w0.15: v1@16.05,10.016 16.05,7.3 18.685,4.665 CN2.7@18.685,3.65 ; CN2.7@18.535,3.65 CN2.7@18.685,3.65 ; CN2.7 CN2.7@18.685,3.65 ; CN2.7@19.002,3.709 18.943,3.65 CN2.7@18.685,3.65
  other v1: 16.022,10.04
PB14: CN2.5 U1.F1 | length 13.3
  Top Layer w0.1: v2(28.478,12.646) 28.478,13.353 29.012,13.887 U1.F1@29.012,14.121
  Signal Layer 1 w0.1: v2(28.478,12.646) 28.487,12.637 28.487,12.33
  Signal Layer 1 w0.15: CN2.5 25.4,5.135 25.4,8.825 25.6,9.025 26.5,9.025 28.487,11.012 28.487,12.33
PB15: CN2.3 U1.G2 | length 12.5
  Top Layer w0.1: v2@29.112,12.649 29.112,13.693 29.29,13.871 29.29,14.342 29.212,14.419 U1.G2@29.212,14.467
  Signal Layer 1 w0.1: 29.112,12.45 v2(29.112,12.646)
  Signal Layer 1 w0.15: CN2.3 27.25,5.095 27.25,8.975 29.112,10.837 29.112,12.45
RF_OUT: C3.1 U1.N5 | length 0.9
  Top Layer w0.3: U1.N5@30.442,15.494 C3.1
RSTN: C6.1 CN2.9 U1.B5 | length 31.9
  Top Layer w0.1: 27.286,16.814 27.719,16.381 27.719,15.736 27.949,15.506 U1.B5@28.213,15.506
  Top Layer w0.15: v1(19.65,19.65) 24,19.65 25.507,18.143 25.507,17.993 26.107,17.993 27.286,16.814
  Signal Layer 1 w0.15: CN2.9@13.55,3.55 13.75,3.75 13.75,18.122 ; 13.75,18.15 15.25,19.65 v1(19.65,19.65)
SMA_IN: CN3.1 U2.A1 | length 5.3
  Top Layer w0.32: U2.A1 34.363,15.5
  Top Layer w0.7: 34.825,15.5 CN3.1
VCAP_A4: C13.2 U1.A4 | length 3.1
  Top Layer w0.1: 27.25,16.25 27.46,16.04 27.46,15.706 28.006,15.16 U1.A4@28.013,15.16
  Top Layer w0.2: C13.2@26,17.2 26.3,17.2 27.25,16.25
VDD: C7.2 C8.2 CN2.1 SB1.2 SB4.2 U1.B1 | length 39
  Top Layer w0.1: U1.B1@28.193,14.114 U1.B1
  Top Layer w0.15: 27.15,13.85 27.25,13.95 28.029,13.95 U1.B1@28.193,14.114
  Top Layer w0.3: v1(25.25,13.85) 25.9,13.85 25.95,13.9 25.975,13.875 26.625,13.875 26.65,13.85 27.05,13.85
  Top Layer w0.5: v1(25.3,19.6) SB4.2 ; v1(32.75,10.3) SB1.2
  Signal Layer 2 w0.5: 22.553,12.55 24.65,12.55 25.25,13.15 v1(25.25,13.85) ; 22.553,13.012 22.553,9.751 23.38,8.924 31.784,8.924 32.75,9.889 v1@32.75,10.316 ; 22.553,13.034 22.553,17.894 24.259,19.6 v1(25.3,19.6) ; 29.541,8.931 29.541,7.659 31.535,5.665 32.983,5.665 33.852,4.796 33.852,3.573 CN2.1
VDD2_A6_IN: C11.2 C12.2 SB4.1 U1.A6 | length 3.9
  Top Layer w0.1: 27.812,16.903 27.925,16.789 27.925,16.088 27.984,16.03 U1.A6@27.984,15.881
  Top Layer w0.2: C12.2@27.7,17.918 ccw(c27.501,17.933) C12.2@27.7,17.95 ; C12.2@27.708,17.677 27.708,17.007 27.812,16.903
  Top Layer w0.28: C11.2@27.55,18.75 27.65,18.65 27.65,18 C12.2@27.7,17.95
  Top Layer w0.5: SB4.1@26.99,19.6 26.99,19.57 27.545,19.015 27.545,18.755 C11.2@27.55,18.75
VDDRF_M2_IN: C1.2 C2.2 SB1.1 U1.M2 | length 3.8
  Top Layer w0.1: U1.M2@30.242,14.467 30.724,14.467 30.967,14.224
  Top Layer w0.3: 30.967,14.224 C2.2@31.721,13.47 ; C2.2@31.788,13.488 31.788,13.431 C1.2@32.422,12.797 ; C1.2@32.45,12.85 32.555,12.745 C1.2@32.555,12.654
  Top Layer w0.5: C1.2@32.555,12.654 32.72,12.489 32.72,12.03 32.725,12.025 32.75,12.025
VFBSD_B3_IN: C9.2 C10.2 L1.1 U1.B3 | length 6.1
  Top Layer w0.1: 27.64,15.06 27.672,15.06 27.925,14.807 28.206,14.807 U1.B3@28.213,14.813
  Top Layer w0.3: L1.1 23.946,15.271 23.946,15.924 24.422,16.4 C9.2 26.524,16.4 26.7,16.224 26.7,15.85 26.8,15.75 26.8,15.625 27.365,15.06 27.64,15.06
VLXSD_D1_OUT: L2.2 U1.D1 | length 1.7
  Top Layer w0.1: 28.3,13.727 28.327,13.727 28.584,13.984 28.584,14.092 U1.D1@28.613,14.12
  Top Layer w0.3: L2.2 27.83,12.73 27.83,13.23 28.3,13.7
XTAL_32K_0: C4.1 SB2.1 U1.D3 X2.1 | length 18
  Top Layer w0.15: 18.482,10.61 18.482,10.068 v1(18.5,10.05) ; SB2.1@18.5,10.725 18.65,10.875 18.65,12.15 X2.1@18.8,12.15 ; X2.1 C4.1
  Signal Layer 1 w0.1: 27.84,12.484 27.84,12.821 28.022,13.003 28.022,13.536 28.414,13.928 28.414,14.615 v2(28.613,14.813)
  Signal Layer 1 w0.15: v1@18.45,10.096 18.548,9.998 18.548,9.702 18.75,9.5 20.35,9.5 21.239,10.389 27.139,10.389 27.84,11.09 27.84,12.484
XTAL_32K_1: C5.2 SB3.1 U1.F3 X2.2 | length 20.3
  Top Layer w0.15: v1@16.9,9.991 16.9,10.615 17.025,10.74 SB3.1@17.025,10.75 ; X2.2@17.05,12.2 C5.2 ; 17.1,10.75 17.1,11.95 17.3,12.15 X2.2@17.25,12.2
  Signal Layer 1 w0.1: 28.15,12.33 28.15,12.778 28.272,12.9 28.272,13.296 28.813,13.836 28.813,14.613 v2(29.013,14.813)
  Signal Layer 1 w0.15: v1@16.9,10.024 16.9,9.6 17.3,9.2 20.5,9.2 21.428,10.128 27.236,10.128 ; 27.236,10.133 28.15,11.047 28.15,12.33
  other v1: 16.9,10.05
XTAL_32M_IN: U1.L1 X1.1 | length 2.5
  Top Layer w0.1: U1.L1@30.042,14.12 30.042,12.845 30.442,12.445 30.442,11.934 X1.1
XTAL_32M_OUT: U1.N1 X1.3 | length 4
  Top Layer w0.1: U1.N1@30.442,14.12 30.442,13 30.833,12.609 30.833,10.975 X1.3
pads on no net: MIRE1.1 MIRE2.1 MIRE3.1 MIRE4.1 MIRE5.1 MIRE6.1

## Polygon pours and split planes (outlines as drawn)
GND on Bottom Layer "NONET_L-01_P-001" (solid, remove dead copper, pour order 9): 0,0 43,0 43,31 0,31
GND on Top Layer "NONET_L-01_P-001" (solid, pour order 8): 0,31 0,0 43,0 43,31
GND on Signal Layer 1 "GND_L02_P005" (solid, remove dead copper, pour order 5): 0,31 0,0 43,0 43,31
GND on Signal Layer 2 "NONET_L-01_P-001" (solid, remove dead copper, pour order 1): 0,31 0,0 43,0 43,31

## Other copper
Top Layer:
  pour cut-out: 33.604,15.5 ccw(c33.927,15.5) 33.927,15.177 ccw(c33.927,15.5) 34.25,15.5 ccw(c33.927,15.5) 33.927,15.823 ccw(c33.927,15.5)
  pour cut-out: 32.45,15.5 ccw(c32.773,15.5) 32.773,15.177 ccw(c32.773,15.5) 33.096,15.5 ccw(c32.773,15.5) 32.773,15.823 ccw(c32.773,15.5)
  pour cut-out: 34.3,16.25 33.767,15.717 33.767,15.283 34.3,14.75 43,14.75 43,16.25
  region net SMA_IN: 34.287,15.85 33.937,15.501 34.288,15.15 34.932,15.15 34.932,15.85
  pour cut-out: 27.225,13.075 27.625,13.075 27.625,12.375 27.225,12.375
  pour cut-out: 30.442,15.194 30.442,15.794 32.647,15.794 32.647,15.194
  pour cut-out: 30.32,15.2 30.442,15.078 30.9,15.078 30.9,13.919 30.506,13.526 27.432,13.526 27.432,16.854 30.32,16.854 30.32,15.7
  pour cut-out: 23.025,14.875 24.775,14.875 24.775,13.825 23.025,13.825
  text "1" at 40.731,4.325 h2 r90
  text ".Layer_Name" at 3.5,-21.3 h3
  text ".GTL" at 45.195,-21.3 h3
Signal Layer 1:
  pour cut-out: 34.347,16.25 43.049,16.25 43.054,14.75 34.347,14.75
  pour cut-out: 32.287,16 34.347,16 34.352,14.75 32.287,14.75
  pour cut-out: 30.571,13.538 29.337,13.538 29.346,13.546 29.346,14.96 29.711,15.325 30.257,15.325 30.257,15.632 30.315,15.69 30.315,15.692 30.571,15.692
  pour cut-out: 30.567,16 32.898,16 32.902,15 30.567,15
  pour cut-out: 19.102,20.548 17.448,22.202 17.773,22.527 19.427,20.873
  pour cut-out: 18.168,23.232 17.843,22.907 16.8,23.95 17.125,24.275
  pour cut-out: 28.72,21.45 28.18,21.45 28.18,21.875 28.72,21.875
  pour cut-out: 29.5,18.59 29.167,18.59 29.167,22.75 29.5,22.75
  pour cut-out: 26.36,16.14 27.85,14.65 27.85,13.855 24.7,13.855 24.7,16.14
  text "2" at 40.731,5.382 h2 r90
  text ".Layer_Name" at 3.5,-21.3 h3
  text ".G1" at 45.195,-21.3 h3
Signal Layer 2:
  pour cut-out: 30.571,13.537 29.355,13.537 29.346,13.546 29.346,14.96 29.711,15.325 30.257,15.325 30.257,15.632 30.317,15.692 30.571,15.692
  pour cut-out: 26.36,16.14 27.85,14.65 27.85,13.855 24.85,13.855 24.85,16.14
  text "3" at 40.731,6.832 h2 r90
  text ".Layer_Name" at 3.425,-21.3 h3
  text ".G2" at 45.12,-21.3 h3
Bottom Layer:
  text "4" at 40.725,8.975 h2 r90
  text ".GBL" at 33.992,-21.332 h3
  text ".Layer_Name" at 75.306,-21.332 h3
Multi-Layer:
  pour cut-out: 39.15,9.5 41.15,9.5 41.15,3.85 39.15,3.85

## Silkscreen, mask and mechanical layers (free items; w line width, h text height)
Top Overlay:
  lines w0.2: 24.325,16.575 24.68,16.575 24.665,16.56 ; 25.305,12.3 25.305,13.35 25.455,13.5
  text "MB2202B" at 11.975,9.5 h3 r90
  text ".Layer_Name" at 3.5,-21.3 h3
  text ".GTO" at 45.195,-21.3 h3
Bottom Overlay:
  text "E" at 2.691,26.469 h9 r270
  text "RX" at 13.125,24.119 h1.5 r270
  text "TX" at 23.406,24.119 h1.5 r270
  text "GND" at 33.504,23.083 h1.5 r270
  text "PA10" at 15.691,22.75 h1.5 r270
  text "SWDIO" at 18.676,21.333 h1.5 r270
  text "SWCLK" at 10.591,21.225 h1.5 r270
  text "H" at 2.406,18.725 h10 r270
  text "I" at 2.982,10.306 h9 r270
  text "GND" at 30.941,5.125 h1.5 r270
  text "RSTN" at 13.191,5.1 h1.5 r270
  text "VDD" at 33.325,5.101 h1.5 r270
  text ".GBO" at 33.992,-21.332 h3
  text ".Layer_Name" at 75.306,-21.332 h3
Top Paste:
  text ".Layer_Name" at 3.473,-21.29 h3
  text ".GTP" at 45.168,-21.29 h3
Bottom Paste:
  text ".GBP" at 33.883,-21.317 h3
  text ".Layer_Name" at 75.197,-21.317 h3
Top Solder:
  region: 39.15,9.504 39.15,3.84 41.15,3.84 41.15,9.504
  region: 33.149,14.816 33.149,14.828
  text ".Layer_Name" at 3.498,-21.365 h3
  text ".GTS" at 45.193,-21.365 h3
Bottom Solder:
  text ".GBS" at 33.908,-21.392 h3
  text ".Layer_Name" at 75.222,-21.392 h3
M1-Board Shape:
  lines w0.1: 0,0 43,0 43,31 0,31 0,0 ; 0,0 0,0 ; 40.75,31 40.75,31
M2-Board Dimensions:
  text ".Layer_Name" at 3.5,-21.3 h3
  text ".GM2" at 45.195,-21.3 h3
M14-Top Assembly:
  text ".Layer_Name" at 3.5,-21.3 h3
  text ".GM14" at 45.195,-21.3 h3
M15-Bottom Assembly:
  text ".GM15" at 33.992,-21.332 h3
  text ".Layer_Name" at 75.306,-21.332 h3
Drill Drawing:
  drawing of 196 lines, arcs and shapes, not listed
  text "PCB SPECIFICATIONS :" at -2.5,74.35 h3
  text "PCB : TYPE 3" at 145.912,74.118 h3
  text "A.   MATERIAL :" at -2.5,70.35 h3
  text "FR-4" at 36,70.35 h3
  text "TG-170" at 52.5,70.35 h3
  text "X  TG-150" at 70.75,70.35 h3
  text "TG-140" at 86.75,70.35 h3
  text "ASPECT-RATIO, AXE Z :" at 145.912,68.618 h3
  text "B.   MATERIAL FAMILY :" at -2.5,67.35 h3
  text "N/A" at 36,67.35 h3
  text "C.   SOLDERMASK COLOR :" at -2.5,64.35 h3
  text "X  GREEN" at 36,64.35 h3
  text "WHITE" at 52.5,64.35 h3
  text "RED" at 70.75,64.35 h3
  text "BLACK" at 86.75,64.35 h3
  text "6:1 to 8:1 / LEVEL \"B\"" at 145.93,61.87 h3
  text "D.   SILKSCREEN COLOR :" at -2.5,61.35 h3
  text "X  WHITE" at 36,61.35 h3
  text "YELLOW" at 52.5,61.35 h3
  text "BLACK" at 70.75,61.35 h3
  text "Blue ink PANTONE 2955" at 86.75,61.35 h3
  text "E.   SURFACE FINISH :" at -2.5,58.35 h3
  text "X  ENIG" at 36,58.35 h3
  text "IMMERSION SILVER" at 52.5,58.35 h3
  text "IMMERSION TIN" at 86.75,58.35 h3
  text "MINIMUM PARAMETERS" at 145.957,56.269 h3
  text "HASL" at 36,55.35 h3
  text "HASL (PB-FREE)" at 52.5,55.35 h3
  text "GOLDEN FINGER" at 86.75,55.35 h3
  text "F.   IMPEDANCE CONTROL :" at -2.5,52.35 h3
  text "NO" at 36,52.35 h3
  text "X  YES  (SEE IMPEDANCE TABLE FOR DETAIL INFORMATION)" at 52.5,52.35 h3
  text "DEFAULT" at 145.957,50.769 h3
  text "G.   THROUGH VIA :" at -2.5,49.35 h3
  text "PLUG THE VIAS WHICH ARE COVERED WITH SOLDERMASK ONE OR TWO SIDE." at 36,49.35 h3
  text "PLUG MATERIAL :" at 36,46.35 h3
  text "X  SOLDERMASK" at 61.5,46.35 h3
  text "NON-CONDUCTIVE EPOXY." at 86.75,46.35 h3
  text "TRACKS : 0.1mm           / GAPS : 0.1mm" at 145.957,45.019 h3
  text "H.   STACK-UP :" at -2.5,43.35 h3
  text "SEE LAYER STACK-UP SEQUENCE FOR OVERALL THICKNESS." at 36,43.35 h3
  text "Layer" at 92.651,35.801 h1.52
  text "Name" at 99.027,35.801 h1.52
  text "Material" at 111.35,35.801 h1.52
  text "Thickness" at 124.613,35.801 h1.52
  text "Constant" at 133.71,35.801 h1.52
  text "Top Overlay" at 99.027,32.753 h1.52
  text "Top Solder" at 99.027,29.705 h1.52
  text "Solder Resist" at 111.35,29.705 h1.52
  text "0,020mm" at 124.613,29.705 h1.52
  text "3.5" at 133.71,29.705 h1.52
  text "1" at 92.651,26.657 h1.52
  text "Top Layer" at 99.027,26.657 h1.52
  text "0,035mm" at 124.613,26.657 h1.52
  text "Dielectric 1" at 99.027,23.609 h1.52
  text "TU-768 (1x2113)" at 111.35,23.609 h1.52
  text "0,102mm" at 124.613,23.609 h1.52
  text "4.2" at 133.71,23.609 h1.52
  text "2" at 92.65,20.561 h1.52
  text "Signal Layer 1" at 99.027,20.561 h1.52
  text "0,036mm" at 124.613,20.561 h1.52
  text "Dielectric2" at 99.027,17.513 h1.52
  text "Tu-768 (2x2113)" at 111.35,17.513 h1.52
  text "0,254mm" at 124.613,17.513 h1.52
  text "4.3" at 133.71,17.513 h1.52
  text "3" at 92.651,14.465 h1.52
  text "Signal Layer 2" at 99.027,14.465 h1.52
  text "0,036mm" at 124.613,14.465 h1.52
  text "Dielectric3" at 99.027,11.417 h1.52
  text "TU-768 (1x2113)" at 111.35,11.417 h1.52
  text "0,102mm" at 124.613,11.417 h1.52
  text "4.2" at 133.71,11.417 h1.52
  text "4" at 92.651,8.369 h1.52
  text "Bottom Layer" at 99.027,8.369 h1.52
  text "0,035mm" at 124.613,8.369 h1.52
  text "Bottom Solder" at 99.027,5.321 h1.52
  text "Solder Resist" at 111.35,5.321 h1.52
  text "0,020mm" at 124.613,5.321 h1.52
  text "3.5" at 133.71,5.321 h1.52
  text "Bottom Overlay" at 99.027,2.273 h1.52
  text "Total board thickness:" at 92.651,-0.775 h1.52
  text "0,639mm" at 124.613,-0.775 h1.52
  text "Symbol" at 92.436,-10.722 h1.83
  text "Count" at 99.6,-10.722 h1.83
  text "Hole Size" at 107.022,-10.722 h1.83
  text "Plated" at 120.846,-10.722 h1.83
  text "Hole Type" at 127.137,-10.722 h1.83
  text "Drill Layer Pair" at 136.292,-10.722 h1.83
  text "Via/Pad" at 157.781,-10.722 h1.83
  text "Pad Shape" at 165.282,-10.722 h1.83
  text "Template" at 175.082,-10.722 h1.83
  text "Hole Length" at 183.694,-10.722 h1.83
  text "Routed Path Length" at 194.172,-10.722 h1.83
  text "14" at 99.6,-13.882 h1.52
  text "0.100mm (3.94mil)" at 107.022,-13.882 h1.52
  text "PTH" at 120.846,-13.882 h1.52
  text "Round" at 127.137,-13.882 h1.52
  text "[uVia] Top Layer - Signal Layer 1" at 136.292,-13.882 h1.52
  text "Via" at 157.781,-13.882 h1.52
  text "Rounded" at 165.282,-13.882 h1.52
  text "v25h10m0" at 175.082,-13.882 h1.52
  text "-" at 183.694,-13.882 h1.52
  text "-" at 194.172,-13.882 h1.52
  text "24" at 99.6,-17.042 h1.52
  text "1.000mm (39.37mil)" at 107.022,-17.042 h1.52
  text "PTH" at 120.846,-17.042 h1.52
  text "Round" at 127.137,-17.042 h1.52
  text "Top Layer - Bottom Layer" at 136.292,-17.042 h1.52
  text "Pad" at 157.781,-17.042 h1.52
  text "Rounded" at 165.282,-17.042 h1.52
  text "(Mixed)" at 175.082,-17.042 h1.52
  text "-" at 183.694,-17.042 h1.52
  text "-" at 194.172,-17.042 h1.52
  text "684" at 99.6,-20.202 h1.52
  text "0.200mm (7.87mil)" at 107.022,-20.202 h1.52
  text "PTH" at 120.846,-20.202 h1.52
  text "Round" at 127.137,-20.202 h1.52
  text "Top Layer - Bottom Layer" at 136.292,-20.202 h1.52
  text "Via" at 157.781,-20.202 h1.52
  text "Rounded" at 165.282,-20.202 h1.52
  text "(Mixed)" at 175.082,-20.202 h1.52
  text "-" at 183.694,-20.202 h1.52
  text "-" at 194.172,-20.202 h1.52
  text ".Layer_Name" at 3.5,-21.3 h3
  text ".DRL" at 45.195,-21.3 h3
  text "722 Total" at 99.6,-23.362 h1.52
M20-Top Title Box:
  circle w0.254: c81.504,-28.021 r1.3
  region: 81.03,-20.784 65.502,-20.784 64.808,-22.56 63.597,-23.785 62.2,-21.925 62.2,-20.274 63.343,-18.877 64.779,-18.498 81.03,-18.498
  region: 67.026,-29.114 56.27,-29.114 57.264,-26.621 65.121,-26.621 65.57,-25.862 67.779,-28.41
  lines w0.254: 57.264,-26.621 66.056,-26.621 62.989,-23.083 cw(c64.793,-21.139) 65.033,-18.498 81.797,-18.498 81.035,-20.784 ; 60.577,-18.251 cw(c63.004,-19.222) 63.24,-16.619 ; 60.617,-18.219 56.27,-29.114 75.593,-29.114 ccw(c75.842,-26.379) 78.391,-27.399 ; 62.356,-22.153 67.779,-28.41 ; 62.61,-22.153 67.915,-28.275 ; 62.61,-21.899 67.915,-28.021 ; 62.708,-20.784 75.701,-20.784 ; 62.737,-21.772 68.042,-27.894 ; 62.864,-21.645 68.169,-27.767 ; 62.991,-21.518 68.296,-27.64 ; 63.118,-21.391 68.423,-27.513 ; 63.173,-19.439 68.478,-25.56 ; 63.241,-16.619 82.691,-16.619 78.392,-27.397 ; 63.245,-21.264 68.496,-27.323 ; 63.245,-21.01 68.55,-27.132 ; 63.245,-20.756 68.55,-26.878 ; 63.245,-19.867 68.55,-25.989 ; 63.372,-20.629 68.677,-26.751 ; 63.372,-20.248 68.677,-26.37 ; 64.744,-26.634 ccw(c64.849,-26.099) 65.147,-25.642 ; 65.831,-20.771 ccw(c65.805,-21.338) 65.474,-21.8 67.839,-24.529 cw(c66.035,-26.473) 66.768,-29.022 ; 72.112,-28.91 75.001,-20.53 ; 72.334,-28.86 75.203,-20.539 ; 72.461,-28.86 75.33,-20.539 ; 72.715,-28.86 75.584,-20.539 ; 72.969,-28.86 75.838,-20.539 ; 73.223,-28.86 76.092,-20.539 ; 73.477,-28.86 76.346,-20.539 ; 73.731,-28.86 76.6,-20.539 ; 73.985,-28.86 76.854,-20.539 ; 74.239,-28.86 77.108,-20.539 ; 74.448,-28.91 77.337,-20.53 ; 77.337,-20.784 81.03,-20.784 ; 80.361,-20.782 81.123,-18.496 ; 80.527,-20.784 81.289,-18.498 ; 80.781,-20.784 81.543,-18.498
  lines w0.3: -5.5,-33 84.5,-33 84.5,-13 -5.5,-13 ; -5.5,-28 54.5,-28 ; -5.5,-23 54.5,-23 ; -5.5,-18 54.5,-18 ; -5.5,-33 -5.5,-13 ; 34.5,-33 34.5,-18 ; 54.5,-33 54.5,-13 ; 72.112,-28.91 74.448,-28.91
  text "Project: '.Board_Name'" at -4.5,-16.216 h3
  text "Layer:" at -4.5,-21.3 h3
  text "Gerber:" at 35.489,-21.3 h3
  text "Variant: '.VariantName'" at -4.5,-26.3 h3
  text "'.Board_Reference'" at 35.616,-26.3 h3
  text "R" at 80.996,-28.783 h1.52
  text "Date: '.Board_Document_Date'" at -4.5,-31.3 h3
  text "Rev: '.Board_PCB_Revision'" at 35.559,-31.3 h3
M21-Bottom Title Box:
  circle w0.254: c-2.317,-28.021 r1.3
  region: 12.161,-29.114 22.917,-29.114 21.924,-26.621 14.066,-26.621 13.617,-25.862 11.409,-28.41
  region: -1.842,-20.784 13.685,-20.784 14.379,-22.56 15.59,-23.785 16.987,-21.925 16.987,-20.274 15.844,-18.877 14.408,-18.498 -1.842,-18.498
  lines w0.254: -2.356,-18.498 -1.594,-20.784 ; -2.102,-18.498 -1.34,-20.784 ; -1.936,-18.496 -1.174,-20.782 ; -1.848,-20.784 -2.61,-18.498 14.154,-18.498 cw(c14.394,-21.139) 16.198,-23.083 13.132,-26.621 21.924,-26.621 ; -1.842,-20.784 1.85,-20.784 ; 0.795,-27.397 -3.504,-16.619 15.946,-16.619 ; 0.796,-27.399 ccw(c3.346,-26.379) 3.594,-29.114 22.917,-29.114 18.571,-18.219 ; 1.85,-20.53 4.739,-28.91 ; 2.079,-20.539 4.948,-28.86 ; 2.333,-20.539 5.202,-28.86 ; 2.587,-20.539 5.456,-28.86 ; 2.841,-20.539 5.71,-28.86 ; 3.095,-20.539 5.964,-28.86 ; 3.349,-20.539 6.218,-28.86 ; 3.486,-20.784 16.479,-20.784 ; 3.603,-20.539 6.472,-28.86 ; 3.857,-20.539 6.726,-28.86 ; 3.984,-20.539 6.853,-28.86 ; 4.186,-20.53 7.075,-28.91 ; 10.51,-26.751 15.815,-20.629 ; 10.51,-26.37 15.815,-20.248 ; 10.637,-27.132 15.942,-21.01 ; 10.637,-26.878 15.942,-20.756 ; 10.637,-25.989 15.942,-19.867 ; 10.691,-27.323 15.942,-21.264 ; 10.709,-25.56 16.014,-19.439 ; 10.764,-27.513 16.069,-21.391 ; 10.891,-27.64 16.196,-21.518 ; 11.018,-27.767 16.323,-21.645 ; 11.145,-27.894 16.45,-21.772 ; 11.272,-28.275 16.577,-22.153 ; 11.272,-28.021 16.577,-21.899 ; 11.409,-28.41 16.831,-22.153 ; 12.419,-29.022 cw(c13.152,-26.473) 11.348,-24.529 13.713,-21.8 ccw(c13.383,-21.338) 13.357,-20.771 ; 14.04,-25.642 ccw(c14.338,-26.099) 14.443,-26.634 ; 15.947,-16.619 cw(c16.184,-19.222) 18.61,-18.251
  lines w0.3: 4.739,-28.91 7.075,-28.91 ; 24.5,-33 24.5,-13 ; 24.5,-28 84.5,-28 ; 24.5,-23 84.5,-23 ; 24.5,-18 84.5,-18 ; 44.5,-33 44.5,-18 ; -5.5,-33 84.5,-33 84.5,-13 -5.5,-13 -5.5,-33
  text "Project: '.Board_Name'" at 83.306,-16.216 h3
  text "Gerber:" at 43.317,-21.3 h3
  text "Layer:" at 83.306,-21.3 h3
  text "'.Board_Reference'" at 43.317,-26.3 h3
  text "Variant: '.VariantName'" at 83.306,-26.3 h3
  text "R" at -1.809,-28.783 h1.52
  text "Rev: '.Board_PCB_Revision'" at 43.374,-31.3 h3
  text "Date: '.Board_Document_Date'" at 83.306,-31.3 h3

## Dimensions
0,31 to 43,31 on M2-Board Dimensions
0,31 to 0,0 on M2-Board Dimensions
